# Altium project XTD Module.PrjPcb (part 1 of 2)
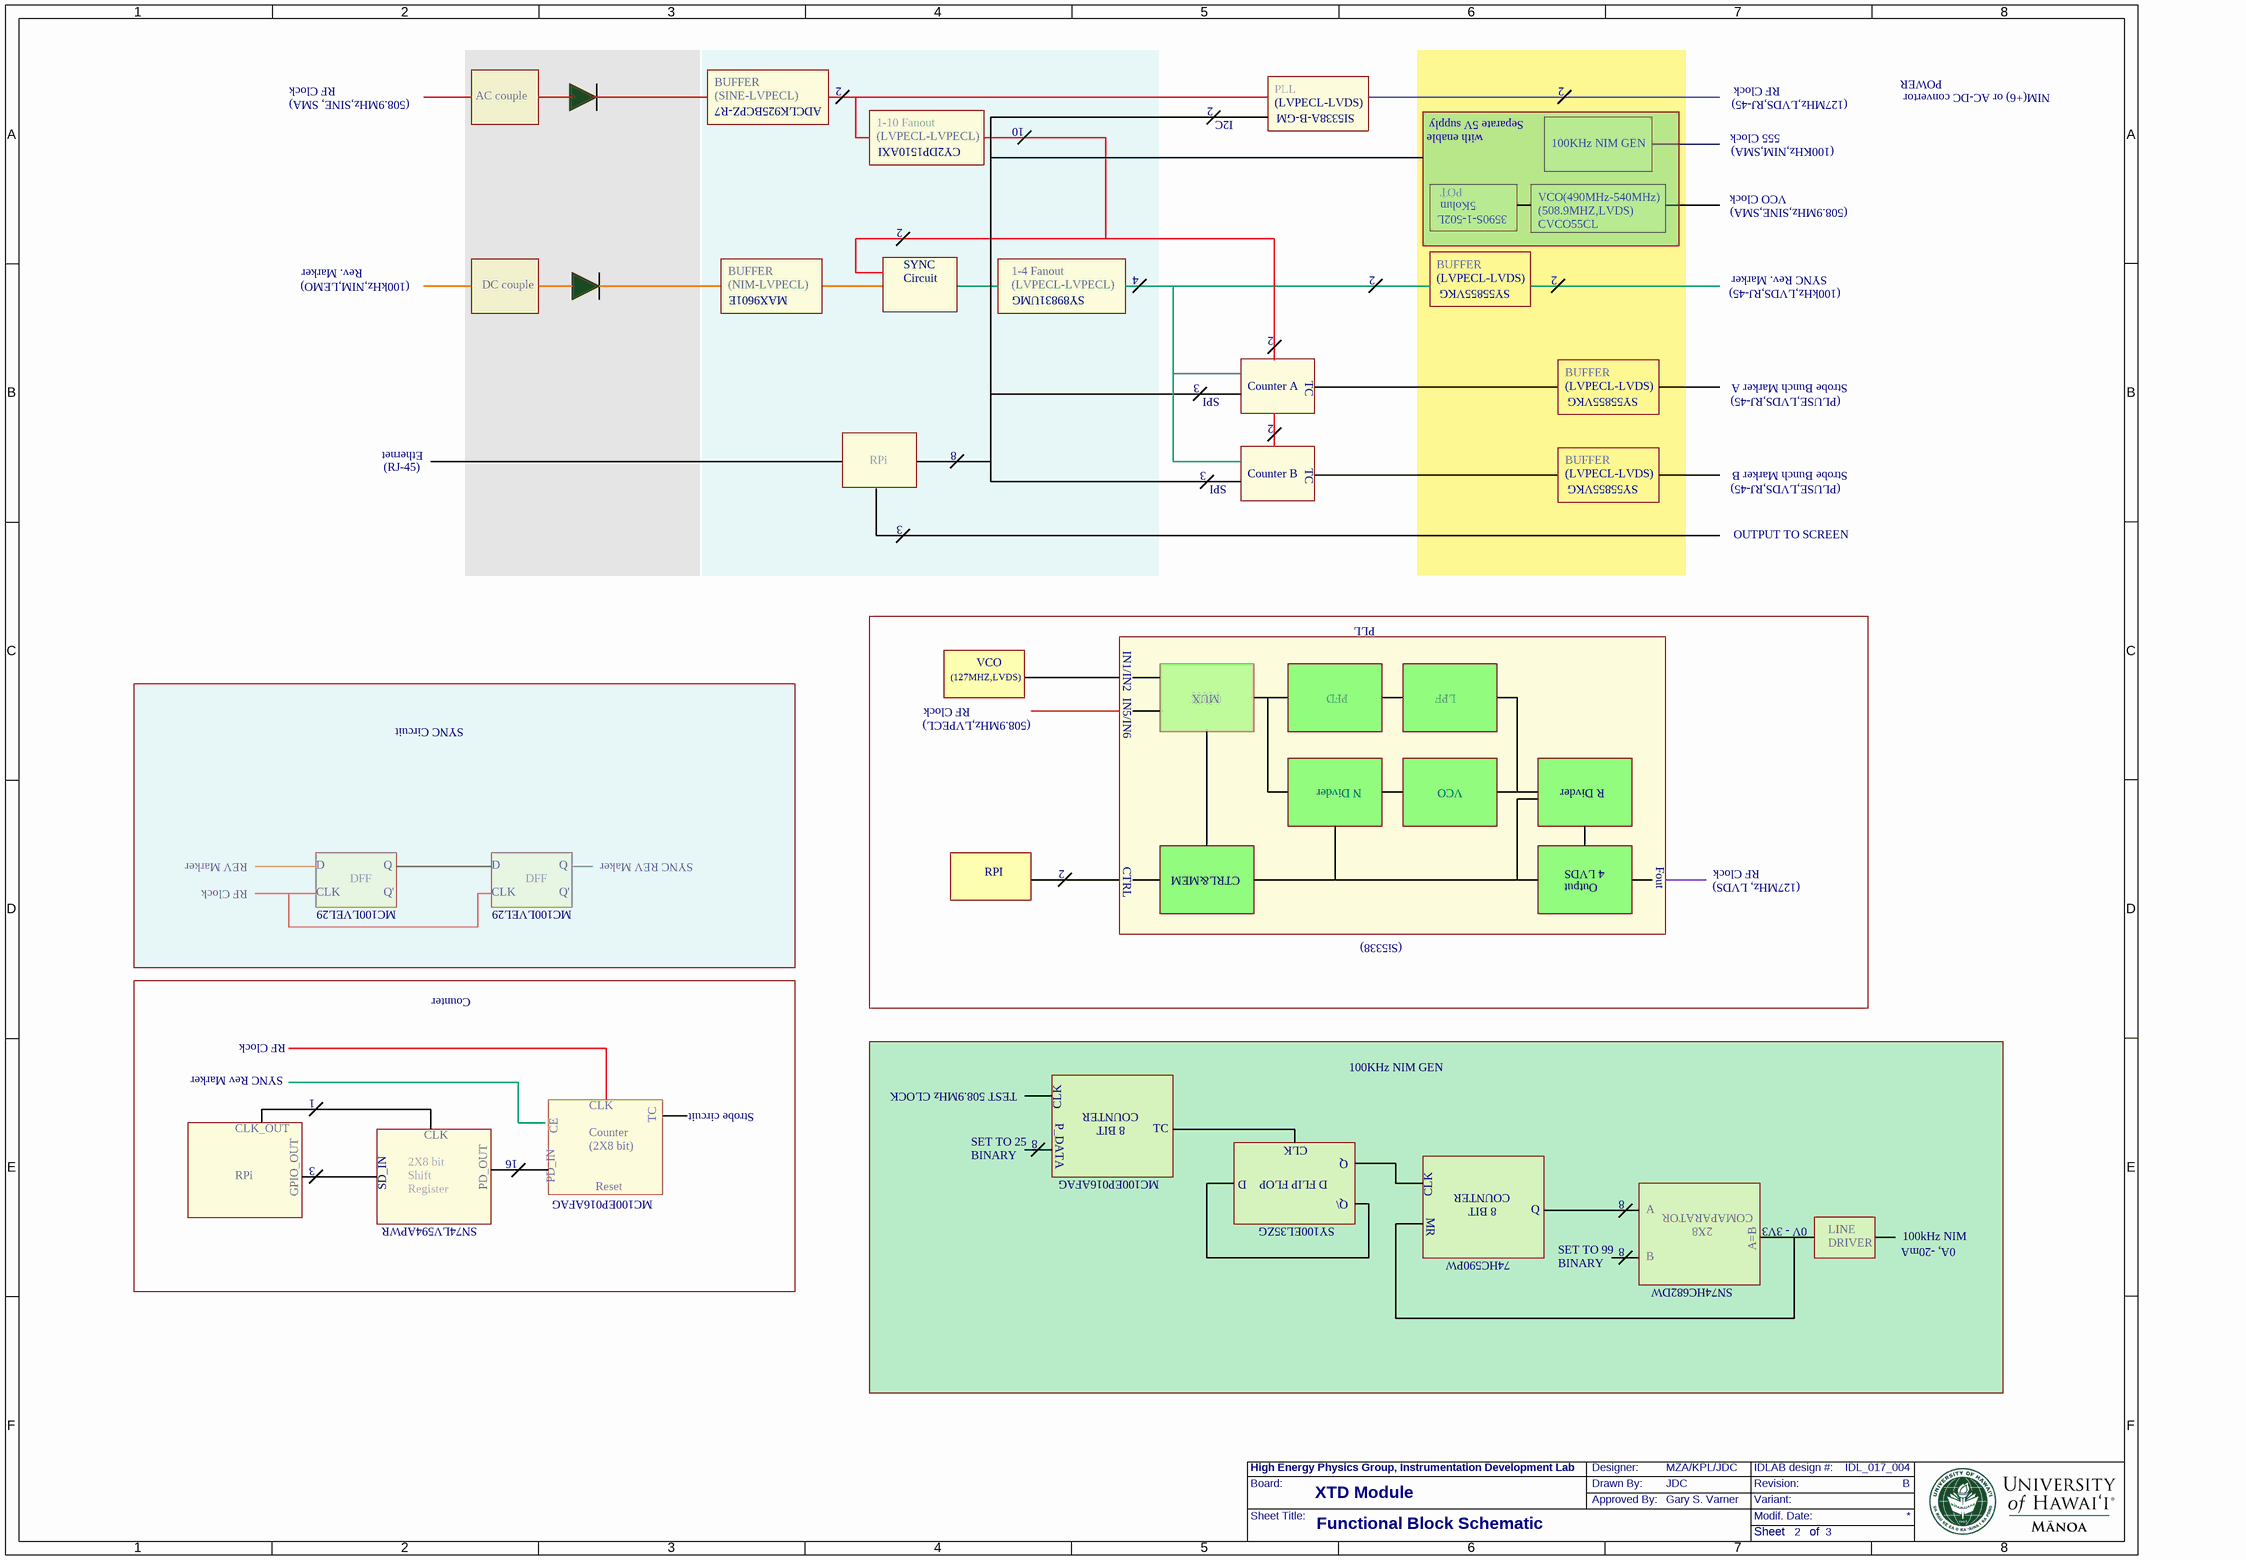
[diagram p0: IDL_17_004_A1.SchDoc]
Approved_By: Gary S. Varner; BoardName: XTD Module; Designer: MZA/KPL/JDC; Drawn_By: JDC; IDLnum: IDL_017_004; ProjectName1: XTD Module; RevNum: B
10 sheets, 403 parts. Net scope: flat (ports and power ports of the same name join across sheets).
Board file: IDL_17_004_A9.PcbDoc
Sheets:
  PRJHdr_IDL_16_XXX_A.SchDoc
  IDL_17_004_A1.SchDoc
  IDL_17_004_A2.SchDoc
  IDL_17_004_A3.SchDoc
  IDL_17_004_A4.SchDoc
  IDL_17_004_A5.SchDoc
  IDL_17_004_A6.SchDoc
  IDL_17_004_A7.SchDoc
  IDL_17_004_A8.SchDoc
  IDL_17_004_WD.SchDoc

## Sheet PRJHdr_IDL_16_XXX_A.SchDoc: Title_doc_parameter!
size 401 x 291 mm; DrawnBy: JDC; DocumentNumber: 1; Revision: B; SheetNumber: 1; SheetTotal: 3; Project_IT-Code: XXXX

## Sheet IDL_17_004_A1.SchDoc: Functional Block Schematic
size 401 x 291 mm; DocumentNumber: 2; SheetNumber: 2; SheetTotal: 3

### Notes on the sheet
- RF Clock
- (508.9MHz,SINE, SMA)
- AC couple
- BUFFER
- (SINE-LVPECL)
- ADCLK925BCPZ-R7
- 2
- PLL
- (127MHz,LVDS,RJ-45)
- POWER
- NIM(+6) or AC-DC convertor
- 1-10 Fanout
- (LVPECL-LVPECL)
- CY2DP1510AXI
- 10
- I2C
- (LVPECL-LVDS)
- SI5338A-B-GM
- with enable
- Separate 5V supply
- 100KHz NIM GEN
- 555 Clock
- (100KHz,NIM,SMA)
- POT
- 5Kohm
- 3590S-1-502L
- VCO(490MHz-540MHz)
- (508.9MHZ,LVDS)
- CVCO55CL
- VCO Clock
- (508.9MHz,SINE,SMA)
- Rev. Marker
- (100kHz,NIM,LEMO)
- DC couple
- (NIM-LVPECL)
- MAX9601E
- SYNC
- Circuit
- 1-4 Fanout
- SY89831UMG
- 4
- SY55855VKG
- SYNC Rev. Marker
- (100kHz,LVDS,RJ-45)
- 3
- SPI
- Counter A
- TC
- (PLUSE,LVDS,RJ-45)
- Strobe Bunch Marker A
- (RJ-45)
- Ethernet
- RPi
- 8
- Counter B
- Strobe Bunch Marker B
- OUTPUT TO SCREEN
- (127MHZ,LVDS)
- VCO
- IN1/IN2
- IN5/IN6
- MUX
- PFD
- LPF
- SYNC Circuit
- (508.9MHz,LVPECL)
- N Divder
- R Divder
- REV Marker
- D
- CLK
- DFF
- Q
- Q'
- MC100LVEL29
- SYNC REV Maker
- RPI
- CTRL
- CTRL&MEM
- Output
- 4 LVDS
- Fout
- (127MHz, LVDS)
- (Si5338)
- Counter
- SYNC Rev Marker
- 1
- Strobe circuit
- TEST 508.9MHz CLOCK
- COUNTER
- CLK_OUT
- Shift
- 2X8 bit
- 16
- PD_IN
- CE
- (2X8 bit)
- SET TO 25
- BINARY
- P_DATA
- 8 BIT
- MC100EP016AFAG
- D FLIP FLOP
- GPIO_OUT
- SD_IN
- Register
- SN74LV594APWR
- PD_OUT
- Reset
- SY100EL35ZG
- Q\
- MR
- A
- 2X8
- COMAPARATOR
- 0V - 3V3
- LINE
- 100kHz NIM
- 0A, -20mA
- 74HC590PW
- SET TO 99
- B
- SN74HC682DW
- A=B
- DRIVER

## Sheet IDL_17_004_A2.SchDoc: Clock Fanout
size 401 x 291 mm; Author: dfsd; DrawnBy: PO/KPL/LVV; DocumentNumber: 3; SheetNumber: 3; SheetTotal: 3
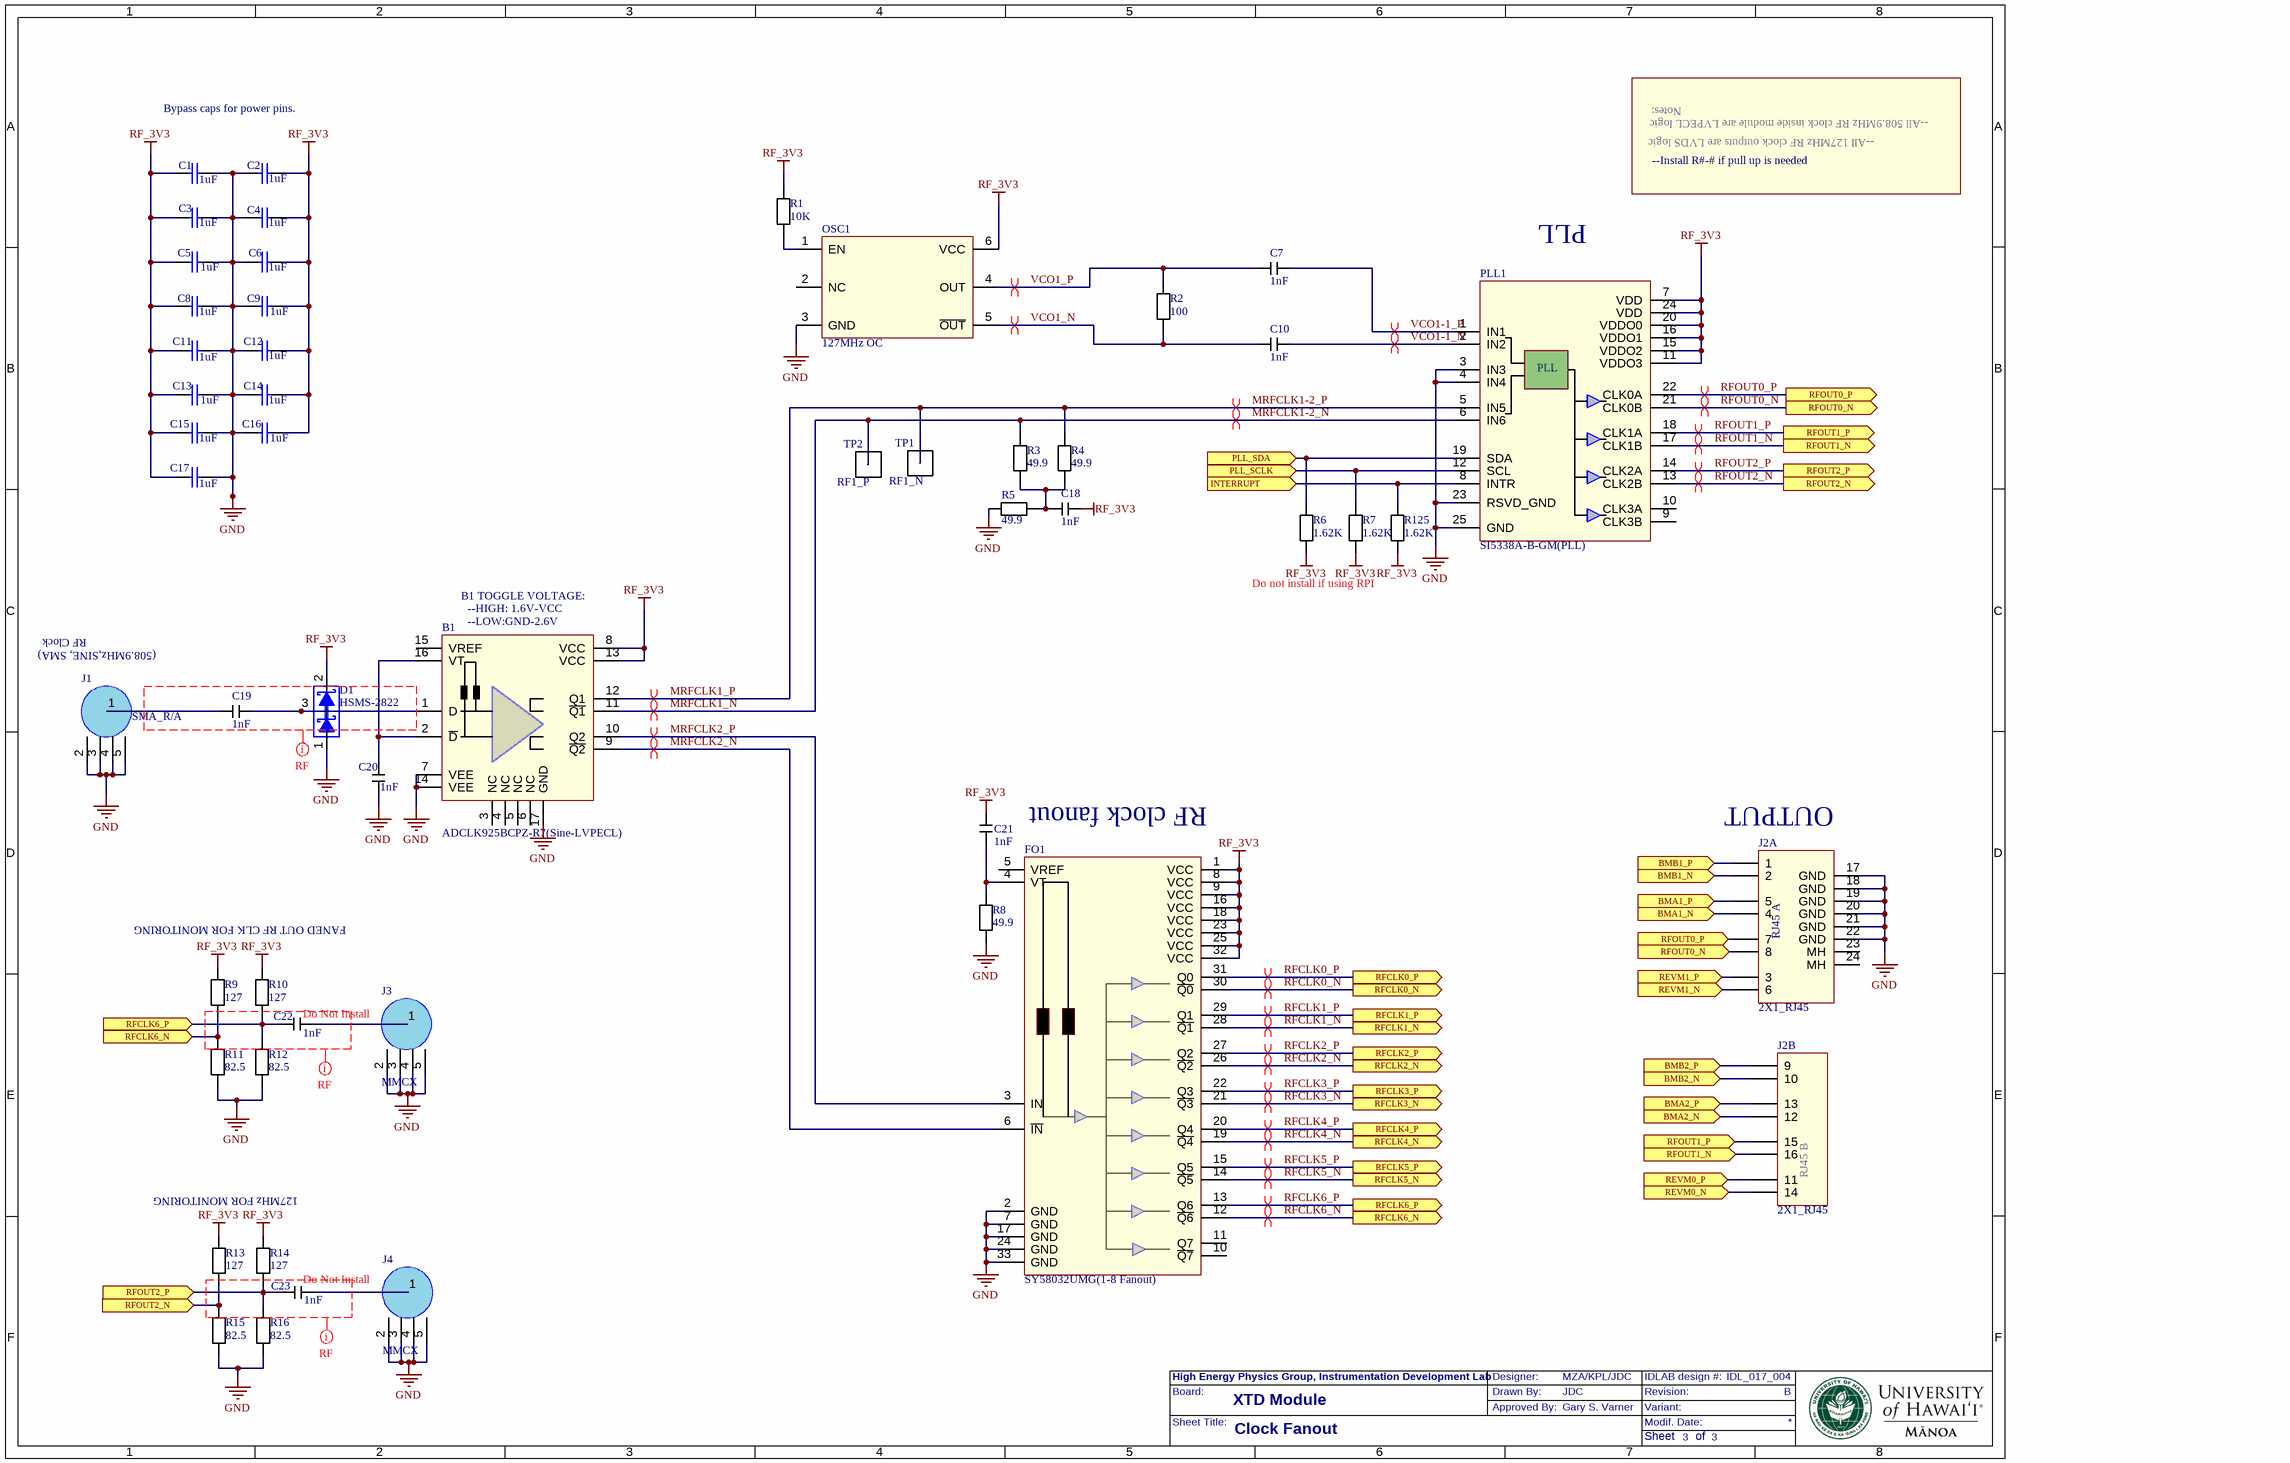
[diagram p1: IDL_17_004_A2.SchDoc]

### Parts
B1  ADCLK925BCPZ-R7(Sine-LVPECL)  [QFN_16pin]
C1  1uF  [0603]
C2  1uF  [0603]
C3  1uF  [0603]
C4  1uF  [0603]
C5  1uF  [0603]
C6  1uF  [0603]
C7  1nF  [0402]
C8  1uF  [0603]
C9  1uF  [0603]
C10  1nF  [0402]
C11  1uF  [0603]
C12  1uF  [0603]
C13  1uF  [0603]
C14  1uF  [0603]
C15  1uF  [0603]
C16  1uF  [0603]
C17  1uF  [0603]
C18  1nF  [0402]
C19  1nF  [0402]
C20  1nF  [0402]
C21  1nF  [0402]
C22  1nF  [0402]
C23  1nF  [0402]
D1  HSMS-2822  [SOT23_3pin]
FO1  SY58032UMG(1-8 Fanout)  [MLF_QFN_32PIN]
J1  SMA_R/A  [SMA_R/A]
J2  2X1_RJ45  [2X1 RJ45]  (parts A,B of 2)
J3  MMCX  [MMCX_VERTICAL_THROUGH_HOLE]
J4  MMCX  [MMCX_VERTICAL_THROUGH_HOLE]
OSC1  127MHz OC  [127MHz OC]
PLL1  SI5338A-B-GM(PLL)  [QFN_24pin]
R1  10K  [0402]
R2  100  [0402]
R3  49.9  [0402]
R4  49.9  [0402]
R5  49.9  [0402]
R6  1.62K  [0402]
R7  1.62K  [0402]
R8  49.9  [0402]
R9  127  [0402]
R10  127  [0402]
R11  82.5  [0402]
R12  82.5  [0402]
R13  127  [0402]
R14  127  [0402]
R15  82.5  [0402]
R16  82.5  [0402]
R125  1.62K  [0402]
TP1  RF1_N  [SMD_TP]
TP2  RF1_P  [SMD_TP]

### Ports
BMA1_N (in), BMA1_P (in), BMA2_N (in), BMA2_P (in), BMB1_N (in), BMB1_P (in), BMB2_N (in), BMB2_P (in), INTERRUPT (in), PLL_SCLK (in), PLL_SDA (in), REVM0_N (in), REVM0_P (in), REVM1_N (in), REVM1_P (in), RFCLK0_N (out), RFCLK0_P (out), RFCLK1_N (out), RFCLK1_P (out), RFCLK2_N (out), RFCLK2_P (out), RFCLK3_N (out), RFCLK3_P (out), RFCLK4_N (out), RFCLK4_P (out), RFCLK5_N (out), RFCLK5_P (out), RFCLK6_N (in), RFCLK6_N (out), RFCLK6_P (in), RFCLK6_P (out), RFOUT0_N (in), RFOUT0_N (out), RFOUT0_P (in), RFOUT0_P (out), RFOUT1_N (in), RFOUT1_N (out), RFOUT1_P (in), RFOUT1_P (out), RFOUT2_N (in), RFOUT2_N (out), RFOUT2_P (in), RFOUT2_P (out)

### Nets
GND: B1.7(VEE) B1.14(VEE) B1.17(GND) C1.2 C2.1 C3.2 C4.1 C5.2 C6.1 C8.2 C9.1 C11.2 C12.1 C13.2 C14.1 C15.2 C16.1 C17.2 C20.1 D1.1(A1) FO1.2(GND) FO1.7(GND) FO1.17(GND) FO1.24(GND) FO1.33(GND) J1.2 J1.3 J1.4 J1.5 J2.17(GND) J2.18(GND) J2.19(GND) J2.20(GND) J2.21(GND) J2.22(GND) J3.2 J3.3 J3.4 J3.5 J4.2 J4.3 J4.4 J4.5 OSC1.3(GND) PLL1.3(IN3) PLL1.4(IN4) PLL1.23(RSVD_GND) PLL1.25(GND) R5.2 R8.1 R11.1 R12.1 R15.1 R16.1
RF_3V3: B1.8(VCC) B1.13(VCC) C1.1 C2.2 C3.1 C4.2 C5.1 C6.2 C8.1 C9.2 C11.1 C12.2 C13.1 C14.2 C15.1 C16.2 C17.1 C18.2 C21.2 D1.2(C2) FO1.1(VCC) FO1.8(VCC) FO1.9(VCC) FO1.16(VCC) FO1.18(VCC) FO1.23(VCC) FO1.25(VCC) FO1.32(VCC) OSC1.6(VCC) PLL1.7(VDD) PLL1.11(VDDO3) PLL1.15(VDDO2) PLL1.16(VDDO1) PLL1.20(VDDO0) PLL1.24(VDD) R1.2 R6.2 R7.1 R9.2 R10.2 R13.2 R14.2 R125.1
BMA1_N: J2.4 ; port BMA1_N
BMA1_P: J2.5 ; port BMA1_P
BMA2_N: J2.12 ; port BMA2_N
BMA2_P: J2.13 ; port BMA2_P
BMB1_N: J2.2 ; port BMB1_N
BMB1_P: J2.1 ; port BMB1_P
BMB2_N: J2.10 ; port BMB2_N
BMB2_P: J2.9 ; port BMB2_P
MRFCLK1-2_N: B1.11(~{Q1}) PLL1.6(IN6) R3.2 TP2.1(TP)  [also labelled MRFCLK1_N]
MRFCLK1-2_P: B1.12(Q1) PLL1.5(IN5) R4.2 TP1.1(TP)  [also labelled MRFCLK1_P]
MRFCLK2_N: B1.9(~{Q2}) FO1.6(~{IN})
MRFCLK2_P: B1.10(Q2) FO1.3(IN)
RFCLK0_N: FO1.30(~{Q0}) ; port RFCLK0_N  [project net RFCLK0-1_N]
RFCLK0_P: FO1.31(Q0) ; port RFCLK0_P  [project net RFCLK0-1_P]
RFCLK1_N: FO1.28(~{Q1}) ; port RFCLK1_N  [project net RFCLK1-1_N]
RFCLK1_P: FO1.29(Q1) ; port RFCLK1_P  [project net RFCLK1-1_P]
RFCLK2_N: FO1.26(~{Q2}) ; port RFCLK2_N  [project net RFCLK2-1_N]
RFCLK2_P: FO1.27(Q2) ; port RFCLK2_P  [project net RFCLK2-1_P]
RFCLK3_N: FO1.21(~{Q3}) ; port RFCLK3_N  [project net RFCLK3-1_N]
RFCLK3_P: FO1.22(Q3) ; port RFCLK3_P  [project net RFCLK3-1_P]
RFCLK4_N: FO1.19(~{Q4}) ; port RFCLK4_N  [project net RFCLK4-1_N]
RFCLK4_P: FO1.20(Q4) ; port RFCLK4_P  [project net RFCLK4-1_P]
RFCLK5_N: FO1.14(~{Q5}) ; port RFCLK5_N  [project net RFCLK5-1_N]
RFCLK5_P: FO1.15(Q5) ; port RFCLK5_P  [project net RFCLK5-1_P]
RFCLK6_N: FO1.12(~{Q6}) R9.1 R11.2 ; port RFCLK6_N
RFCLK6_P: C22.1 FO1.13(Q6) R10.1 R12.2 ; port RFCLK6_P
RFOUT0_N: J2.8 PLL1.21(CLK0B) ; port RFOUT0_N
RFOUT0_P: J2.7 PLL1.22(CLK0A) ; port RFOUT0_P
RFOUT1_N: J2.16 PLL1.17(CLK1B) ; port RFOUT1_N
RFOUT1_P: J2.15 PLL1.18(CLK1A) ; port RFOUT1_P
RFOUT2_N: PLL1.13(CLK2B) R13.1 R15.2 ; port RFOUT2_N
RFOUT2_P: C23.1 PLL1.14(CLK2A) R14.1 R16.2 ; port RFOUT2_P
RMOUT0_N: J2.14 ; port REVM0_N
RMOUT0_P: J2.11 ; port REVM0_P
RMOUT1_N: J2.6 ; port REVM1_N
RMOUT1_P: J2.3 ; port REVM1_P
VCO1-1_N: C10.2 PLL1.2(IN2)
VCO1-1_P: C7.2 PLL1.1(IN1)
VCO1_N: C10.1 OSC1.5(~{OUT}) R2.1
VCO1_P: C7.1 OSC1.4(OUT) R2.2
Net*_3: PLL1.19(SDA) R6.1 ; port PLL_SDA
Net*_5: PLL1.12(SCL) R7.2 ; port PLL_SCLK
Net*_21: PLL1.8(INTR) R125.2 ; port INTERRUPT
NetB1_1: B1.1(D) C19.2 D1.3(C1A2)
NetB1_2: B1.2(~{D}) B1.16(VT) C20.2
NetC18_1: C18.1 R3.1 R4.1 R5.1
NetC19_1: C19.1 J1.1
NetC21_1: C21.1 FO1.4(VT) R8.2
NetC22_2: C22.2 J3.1
NetC23_2: C23.2 J4.1
NetOSC1_1: OSC1.1(EN) R1.1

Not connected (* = marked no-connect by the designer): B1 3(NC) 4(NC) 5(NC) 6(NC) 15(VREF); FO1 5(VREF) 10(~{Q7}) 11(Q7); J2 23(MH) 24(MH); OSC1 2(NC); PLL1 9(CLK3B) 10(CLK3A)

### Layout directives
differential pair: MRFCLK1-2_N, MRFCLK1-2_P, MRFCLK2_N, MRFCLK2_P, RFCLK0-1_N, RFCLK0-1_P, RFCLK1-1_N, RFCLK1-1_P, RFCLK2-1_N, RFCLK2-1_P, RFCLK3-1_N, RFCLK3-1_P, RFCLK4-1_N, RFCLK4-1_P, RFCLK5-1_N, RFCLK5-1_P, RFCLK6_N, RFCLK6_P, RFOUT0_N, RFOUT0_P, RFOUT1_N, RFOUT1_P, RFOUT2_N, RFOUT2_P, VCO1-1_N, VCO1-1_P, VCO1_N, VCO1_P
net class RF: (no net found under the mark)

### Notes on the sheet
- Bypass caps for power pins.
- Notes:
- --All 127MHz RF clock outputs are LVDS logic
- --All 508.9MHz RF clock inside module are LVPECL logic
- PLL
- --Install R#-# if pull up is needed
- (near B1) B1 TOGGLE VOLTAGE:
- Do not install if using RPI
- RF Clock
- (508.9MHz,SINE, SMA)
- (near B1) --HIGH: 1.6V-VCC
- (near B1) --LOW:GND-2.6V
- (near C21) RF clock fanout
- (near J2) OUTPUT
- FANED OUT RF CLK FOR MONITORING
- Do Not Install
- 127MHz FOR MONITORING

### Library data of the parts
B1 = ADCLK925BCPZ-R7(Sine-LVPECL): IC CLK BUFFER 1:2 7.5GHZ 16LFCSP; Manufacturer: Analog Devices Inc.
C1-C6 C8 C9 C11-C17 = 1uF: CAP CER 1UF 25V X7R 0603; Tech: SMDR; Voltage rating: 50V
C7 C10 C18-C23 = 1nF: CAP CER 1000PF 50V X7R 0402; Manufacturer: Samsung Electro-Mechanics America, Inc.; Manufacturer part #: CL05B102KB5NNNC
D1 = HSMS-2822(seires diode): Surface Mount RF Schottky Barrier Diodes, Series Config.; Manufacturer: Avago; Manufacturer No: HSMS-2822-TR1G; Tech: SMDR
FO1 = SY58032UMG(1-8 Fanout): IC CLK BUFFER 1:8 4GHZ 32MLF; Manufacturer: Micrel Inc.
J1 = SMA_R/A: CONN SMA JACK R/A 50 OHM PCB; Manufacturer: Molex, LLC; Manufacturer part #: 0732512201
J2 = 2X1_RJ45: CONN MOD JACK 8P8C R/A SHIELDED; Manufacturer: EDAC Inc.; Manufacturer part #: A00-216-672-450
J3 J4 = MMCX: CONN MMCX JACK STR 50 OHM PCB; Manufacturer: Molex, LLC; Manufacturer part #: 0734151471
OSC1 = 127MHz OC: OSC VCO 127.21MHZ
PLL1 = SI5338A-B-GM(PLL): IC CLK GEN I2C BUS PROG 24QFN; Manufacturer: Silicon Labs
R1 = 10K: RES SMD 10K OHM 5% 1/16W 0402; Manufacturer: Samsung Electro-Mechanics America, Inc.; Manufacturer part #: RC1005F4021CS
R2 = 100: RES SMD 100 OHM 5% 1/16W 0402; Manufacturer: Samsung Electro-Mechanics America, Inc.; Manufacturer part #: RC1005J101CS
R3-R5 R8 = 49.9: RES SMD 49.9 OHM 1% 1/16W 0402; Manufacturer: Samsung Electro-Mechanics America, Inc.; Manufacturer part #: RC1005F49R9CS
R6 R7 R125 = 1.62K: RES SMD 1.62K OHM 1% 1/16W 0402; Manufacturer: Samsung Electro-Mechanics America, Inc.; Manufacturer part #: RC1005F1621CS
R9 R10 R13 R14 = 127: RES SMD 127 OHM 1% 1/16W 0402; Manufacturer: Samsung Electro-Mechanics America, Inc.; Manufacturer part #: RC1005F1270CS
R11 R12 R15 R16 = 82.5: RES SMD 82.5 OHM 1% 1/16W 0402; Manufacturer: Samsung Electro-Mechanics America, Inc.; Manufacturer part #: RC1005F82R5CS
TP1 TP2 = SMD_TP: SURFACE MOUNT TEST POINT

## Sheet IDL_17_004_A3.SchDoc: Revalution Marker Fanout
size 401 x 291 mm
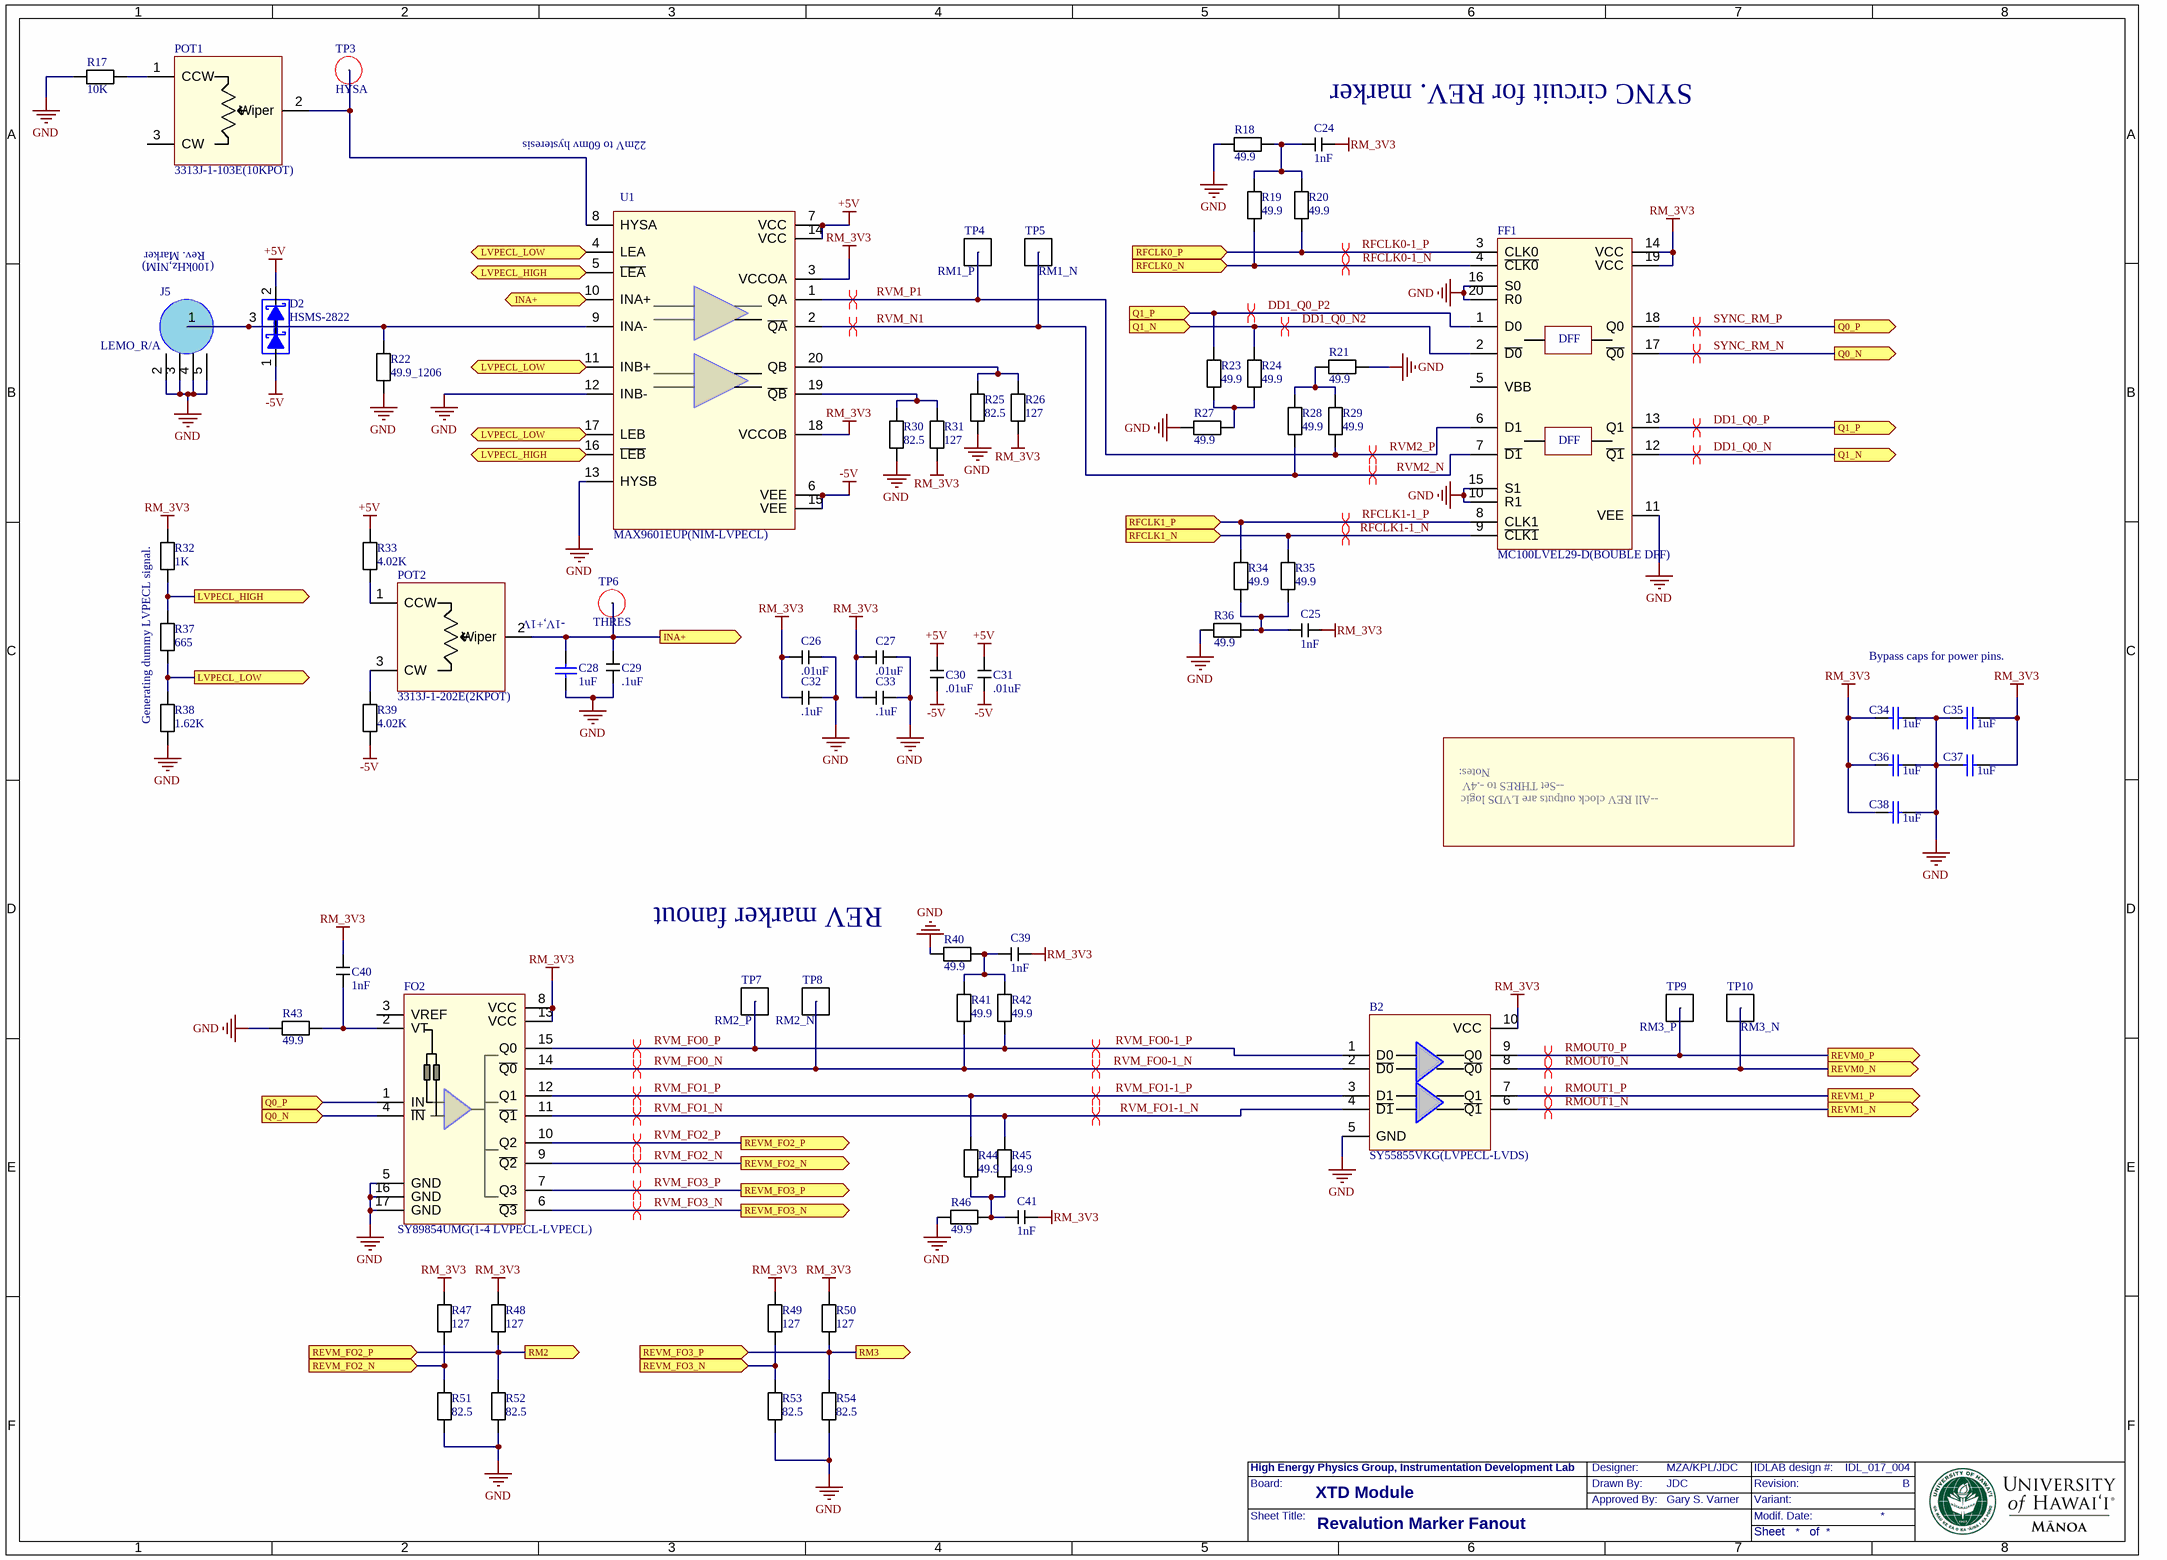
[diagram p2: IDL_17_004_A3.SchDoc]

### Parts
B2  SY55855VKG(LVPECL-LVDS)  [TFSOP_10pin]
C24  1nF  [0402]
C25  1nF  [0402]
C26  .01uF  [0603]
C27  .01uF  [0603]
C28  1uF  [0603]
C29  .1uF  [0603]
C30  .01uF  [0603]
C31  .01uF  [0603]
C32  .1uF  [0603]
C33  .1uF  [0603]
C34  1uF  [0603]
C35  1uF  [0603]
C36  1uF  [0603]
C37  1uF  [0603]
C38  1uF  [0603]
C39  1nF  [0402]
C40  1nF  [0402]
C41  1nF  [0402]
D2  HSMS-2822  [SOT23_3pin]
FF1  MC100LVEL29-D(BOUBLE DFF)  [SOIC_20pin]
FO2  SY89854UMG(1-4 LVPECL-LVPECL)  [VFQFN_16PIN]
J5  LEMO_R/A  [LEMO_R/A]
POT1  3313J-1-103E(10KPOT)  [2KPOT]
POT2  3313J-1-202E(2KPOT)  [2KPOT]
R17  10K  [0402]
R18  49.9  [0402]
R19  49.9  [0402]
R20  49.9  [0402]
R21  49.9  [0402]
R22  49.9_1206  [RC1206N1X]
R23  49.9  [0402]
R24  49.9  [0402]
R25  82.5  [0402]
R26  127  [0402]
R27  49.9  [0402]
R28  49.9  [0402]
R29  49.9  [0402]
R30  82.5  [0402]
R31  127  [0402]
R32  1K  [0402]
R33  4.02K  [0402]
R34  49.9  [0402]
R35  49.9  [0402]
R36  49.9  [0402]
R37  665  [0402]
R38  1.62K  [0402]
R39  4.02K  [0402]
R40  49.9  [0402]
R41  49.9  [0402]
R42  49.9  [0402]
R43  49.9  [0402]
R44  49.9  [0402]
R45  49.9  [0402]
R46  49.9  [0402]
R47  127  [0402]
R48  127  [0402]
R49  127  [0402]
R50  127  [0402]
R51  82.5  [0402]
R52  82.5  [0402]
R53  82.5  [0402]
R54  82.5  [0402]
TP3  HYSA  [Test Point]
TP4  RM1_P  [SMD_TP]
TP5  RM1_N  [SMD_TP]
TP6  THRES  [Test Point]
TP7  RM2_P  [SMD_TP]
TP8  RM2_N  [SMD_TP]
TP9  RM3_P  [SMD_TP]
TP10  RM3_N  [SMD_TP]
U1  MAX9601EUP(NIM-LVPECL)  [TSSOP_20pin]

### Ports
INA+ (in), INA+ (out), LVPECL_HIGH (in), LVPECL_HIGH (out), LVPECL_LOW (in), LVPECL_LOW (out), Q0_N (in), Q0_N (out), Q0_P (in), Q0_P (out), Q1_N (in), Q1_N (out), Q1_P (in), Q1_P (out), REVM0_N (out), REVM0_P (out), REVM1_N (out), REVM1_P (out), REVM_FO2_N (in), REVM_FO2_N (out), REVM_FO2_P (in), REVM_FO2_P (out), REVM_FO3_N (in), REVM_FO3_N (out), REVM_FO3_P (in), REVM_FO3_P (out), RFCLK0_N (in), RFCLK0_P (in), RFCLK1_N (in), RFCLK1_P (in), RM2 (out), RM3 (out)

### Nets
+5V: C30.2 C31.2 D2.2(C2) R33.2 U1.7(VCC) U1.14(VCC)
-5V: C30.1 C31.1 D2.1(A1) R39.1 U1.6(VEE) U1.15(VEE)
GND: B2.5(GND) C26.2 C27.2 C28.1 C29.1 C32.1 C33.1 C34.2 C35.1 C36.2 C37.1 C38.2 FF1.10(R1) FF1.11(VEE) FF1.15(S1) FF1.16(S0) FF1.20(R0) FO2.5(GND) FO2.16(GND) FO2.17(GND) J5.2 J5.3 J5.4 J5.5 R17.1 R18.2 R21.2 R22.1 R25.1 R27.1 R30.1 R36.2 R38.1 R40.2 R43.1 R46.2 R51.1 R52.1 R53.1 R54.1 U1.12(INB-) U1.13(HYSB)
RM_3V3: B2.10(VCC) C24.2 C25.2 C26.1 C27.1 C32.2 C33.2 C34.1 C35.2 C36.1 C37.2 C38.1 C39.2 C40.2 C41.2 FF1.14(VCC) FF1.19(VCC) FO2.8(VCC) FO2.13(VCC) R26.2 R31.2 R32.2 R47.2 R48.2 R49.2 R50.2 U1.3(VCCOA) U1.18(VCCOB)
DD1_Q0_N: FF1.2(~{D0}) FF1.12(~{Q1}) R24.1 ; port Q1_N  [also labelled DD1_Q0_N2]
DD1_Q0_P: FF1.1(D0) FF1.13(Q1) R23.1 ; port Q1_P  [also labelled DD1_Q0_P2]
RFCLK0-1_N: FF1.4(~{CLK0}) R19.1 ; port RFCLK0_N
RFCLK0-1_P: FF1.3(CLK0) R20.1 ; port RFCLK0_P
RFCLK1-1_N: FF1.9(~{CLK1}) R35.2 ; port RFCLK1_N
RFCLK1-1_P: FF1.8(CLK1) R34.2 ; port RFCLK1_P
RMOUT0_N: B2.8(~{Q0}) TP10.1(TP) ; port REVM0_N
RMOUT0_P: B2.9(Q0) TP9.1(TP) ; port REVM0_P
RMOUT1_N: B2.6(~{Q1}) ; port REVM1_N
RMOUT1_P: B2.7(Q1) ; port REVM1_P
RVM2_N: FF1.7(~{D1}) R28.2 TP5.1(TP) U1.2(~{QA})  [also labelled RVM_N1]
RVM2_P: FF1.6(D1) R29.2 TP4.1(TP) U1.1(QA)  [also labelled RVM_P1]
RVM_FO0-1_N: B2.2(~{D0}) FO2.14(~{Q0}) R41.1 TP8.1(TP)  [also labelled RVM_FO0_N]
RVM_FO0-1_P: B2.1(D0) FO2.15(Q0) R42.1 TP7.1(TP)  [also labelled RVM_FO0_P]
RVM_FO1-1_N: B2.4(~{D1}) FO2.11(~{Q1}) R45.2  [also labelled RVM_FO1_N]
RVM_FO1-1_P: B2.3(D1) FO2.12(Q1) R44.2  [also labelled RVM_FO1_P]
RVM_FO2_N: FO2.9(~{Q2}) R47.1 R51.2 ; port REVM_FO2_N
RVM_FO2_P: FO2.10(Q2) R48.1 R52.2 ; port RM2, port REVM_FO2_P
RVM_FO3_N: FO2.6(~{Q3}) R49.1 R53.2 ; port REVM_FO3_N
RVM_FO3_P: FO2.7(Q3) R50.1 R54.2 ; port RM3, port REVM_FO3_P
SYNC_RM_N: FF1.17(~{Q0}) FO2.4(~{IN}) ; port Q0_N
SYNC_RM_P: FF1.18(Q0) FO2.1(IN) ; port Q0_P
NetC24_1: C24.1 R18.1 R19.2 R20.2
NetC25_1: C25.1 R34.1 R35.1 R36.1
NetC28_2: C28.2 C29.2 POT2.2(Wiper) TP6.1(TP) U1.10(INA+) ; port INA+
NetC39_1: C39.1 R40.1 R41.2 R42.2
NetC40_1: C40.1 FO2.2(VT) R43.2
NetC41_1: C41.1 R44.1 R45.1 R46.1
NetD2_3: D2.3(C1A2) J5.1 R22.2 U1.9(INA-)
NetPOT1_1: POT1.1(CCW) R17.2
NetPOT1_2: POT1.2(Wiper) TP3.1(TP) U1.8(HYSA)
NetPOT2_1: POT2.1(CCW) R33.1
NetPOT2_3: POT2.3(CW) R39.2
NetR21_1: R21.1 R28.1 R29.1
NetR23_2: R23.2 R24.2 R27.2
NetR25_2: R25.2 R26.1 U1.20(QB)
NetR30_2: R30.2 R31.1 U1.19(~{QB})
NetR32_1: R32.1 R37.2 U1.5(~{LEA}) U1.16(~{LEB}) ; port LVPECL_HIGH
NetR37_1: R37.1 R38.2 U1.4(LEA) U1.11(INB+) U1.17(LEB) ; port LVPECL_LOW

Not connected (* = marked no-connect by the designer): FF1 5(VBB); FO2 3(VREF); POT1 3(CW)

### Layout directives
differential pair: DD1_Q0_N, DD1_Q0_P, RFCLK0-1_N, RFCLK0-1_P, RFCLK1-1_N, RFCLK1-1_P, RMOUT0_N, RMOUT0_P, RMOUT1_N, RMOUT1_P, RVM2_N, RVM2_P, RVM_FO0-1_N, RVM_FO0-1_P, RVM_FO1-1_N, RVM_FO1-1_P, RVM_FO2_N, RVM_FO2_P, RVM_FO3_N, RVM_FO3_P, SYNC_RM_N, SYNC_RM_P

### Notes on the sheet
- SYNC circuit for REV. marker
- 22mV to 60mv hysteresis
- Rev. Marker
- (100kHz,NIM)
- (near POT2) -1V,+1V
- Bypass caps for power pins.
- Generating dummy LVPECL signal.
- Notes:
- --Set THRES to -.4V
- --All REV clock outputs are LVDS logic
- REV marker fanout

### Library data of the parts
B2 = SY55855VKG(LVPECL-LVDS): IC TRANSLATOR DUAL LVDS 10MSOP; Manufacturer: Micrel Inc.
C24 C25 C39-C41 = 1nF: as C7 on sheet IDL_17_004_A2
C26 C27 C30 C31 = .01uF: CAP CER 10000PF 50V X7R 0603; Manufacturer: Samsung Electro-Mechanics America, Inc.; Manufacturer part #: CL10B103KB8NCNC
C28 C34-C38 = 1uF: as C1 on sheet IDL_17_004_A2
C29 C32 C33 = .1uF: CAP CER 0.1UF 50V X7R 0603; Manufacturer: Samsung Electro-Mechanics America, Inc.; Manufacturer part: CL10B104KB8SFNC
D2 = HSMS-2822(seires diode): as D1 on sheet IDL_17_004_A2
FF1 = MC100LVEL29-D(BOUBLE DFF): IC D-TYPE POS TRG DUAL 20SOIC; Manufacturer: ON Semiconductor; Manufacturer part #: MC100LVEL29DWG
FO2 = SY89854UMG(1-4 LVPECL-LVPECL): IC CLK BUFFER 1:4 3.5GHZ 16MLF; Manufacturer: Micrel Inc.
J5 = LEMO_R/A: CONN JACK R/A 50 OHM PCB; Manufacturer: LEMO; Manufacturer part #: EPL.00.250.NTN
POT1 = 3313J-1-103E(10KPOT): TRIMMER 10K OHM 0.125W SMD; Manufacturer: Bourns Inc.
POT2 = 3313J-1-202E(2KPOT): TRIMMER 2K OHM 0.125W SMD; Manufacturer: Bourns Inc.
R17 = 10K: as R1 on sheet IDL_17_004_A2
R18-R21 R23 R24 R27-R29 R34-R36 R40-R46 = 49.9: as R3 on sheet IDL_17_004_A2
R22 = 49.9_1206: RES SMD 49.9 OHM 1% 1/2W 1206; Manufacturer: Stackpole Electronics Inc.; Manufacturer part #: RNCP1206FTD49R9
R25 R30 R51-R54 = 82.5: as R11 on sheet IDL_17_004_A2
R26 R31 R47-R50 = 127: as R9 on sheet IDL_17_004_A2
R32 = 1K: RES SMD 1K OHM 5% 1/16W 0402; Manufacturer: Samsung Electro-Mechanics America, Inc.; Manufacturer part #: RC1005J102CS
R33 R39 = 4.02K: RES SMD 4.02K OHM 1% 1/16W 0402; Manufacturer: Samsung Electro-Mechanics America, Inc.; Manufacturer part #: RC1005F4021CS
R37 = 665: RES SMD 665 OHM 1% 1/16W 0402; Manufacturer: Samsung Electro-Mechanics America, Inc.; Manufacturer part #: RC1005F6650CS
R38 = 1.62K: as R6 on sheet IDL_17_004_A2
TP3 TP6 = Test point: TEST POINT PC MINI .040"D BLACK; Manufacturer: Keystone Electronics; Manufacturer part #: 5001
TP4 TP5 TP7-TP10 = SMD_TP: SURFACE MOUNT TEST POINT
U1 = MAX9601EUP(NIM-LVPECL): IC COMPARATOR HS 20-TSSOP; Manufacturer: Maxim Integrated; Manufacturer part #: MAX9601EUP+

## Sheet IDL_17_004_A4.SchDoc: Counter A and B
size 401 x 291 mm; DocumentNumber: 3; SheetNumber: 3; SheetTotal: 3
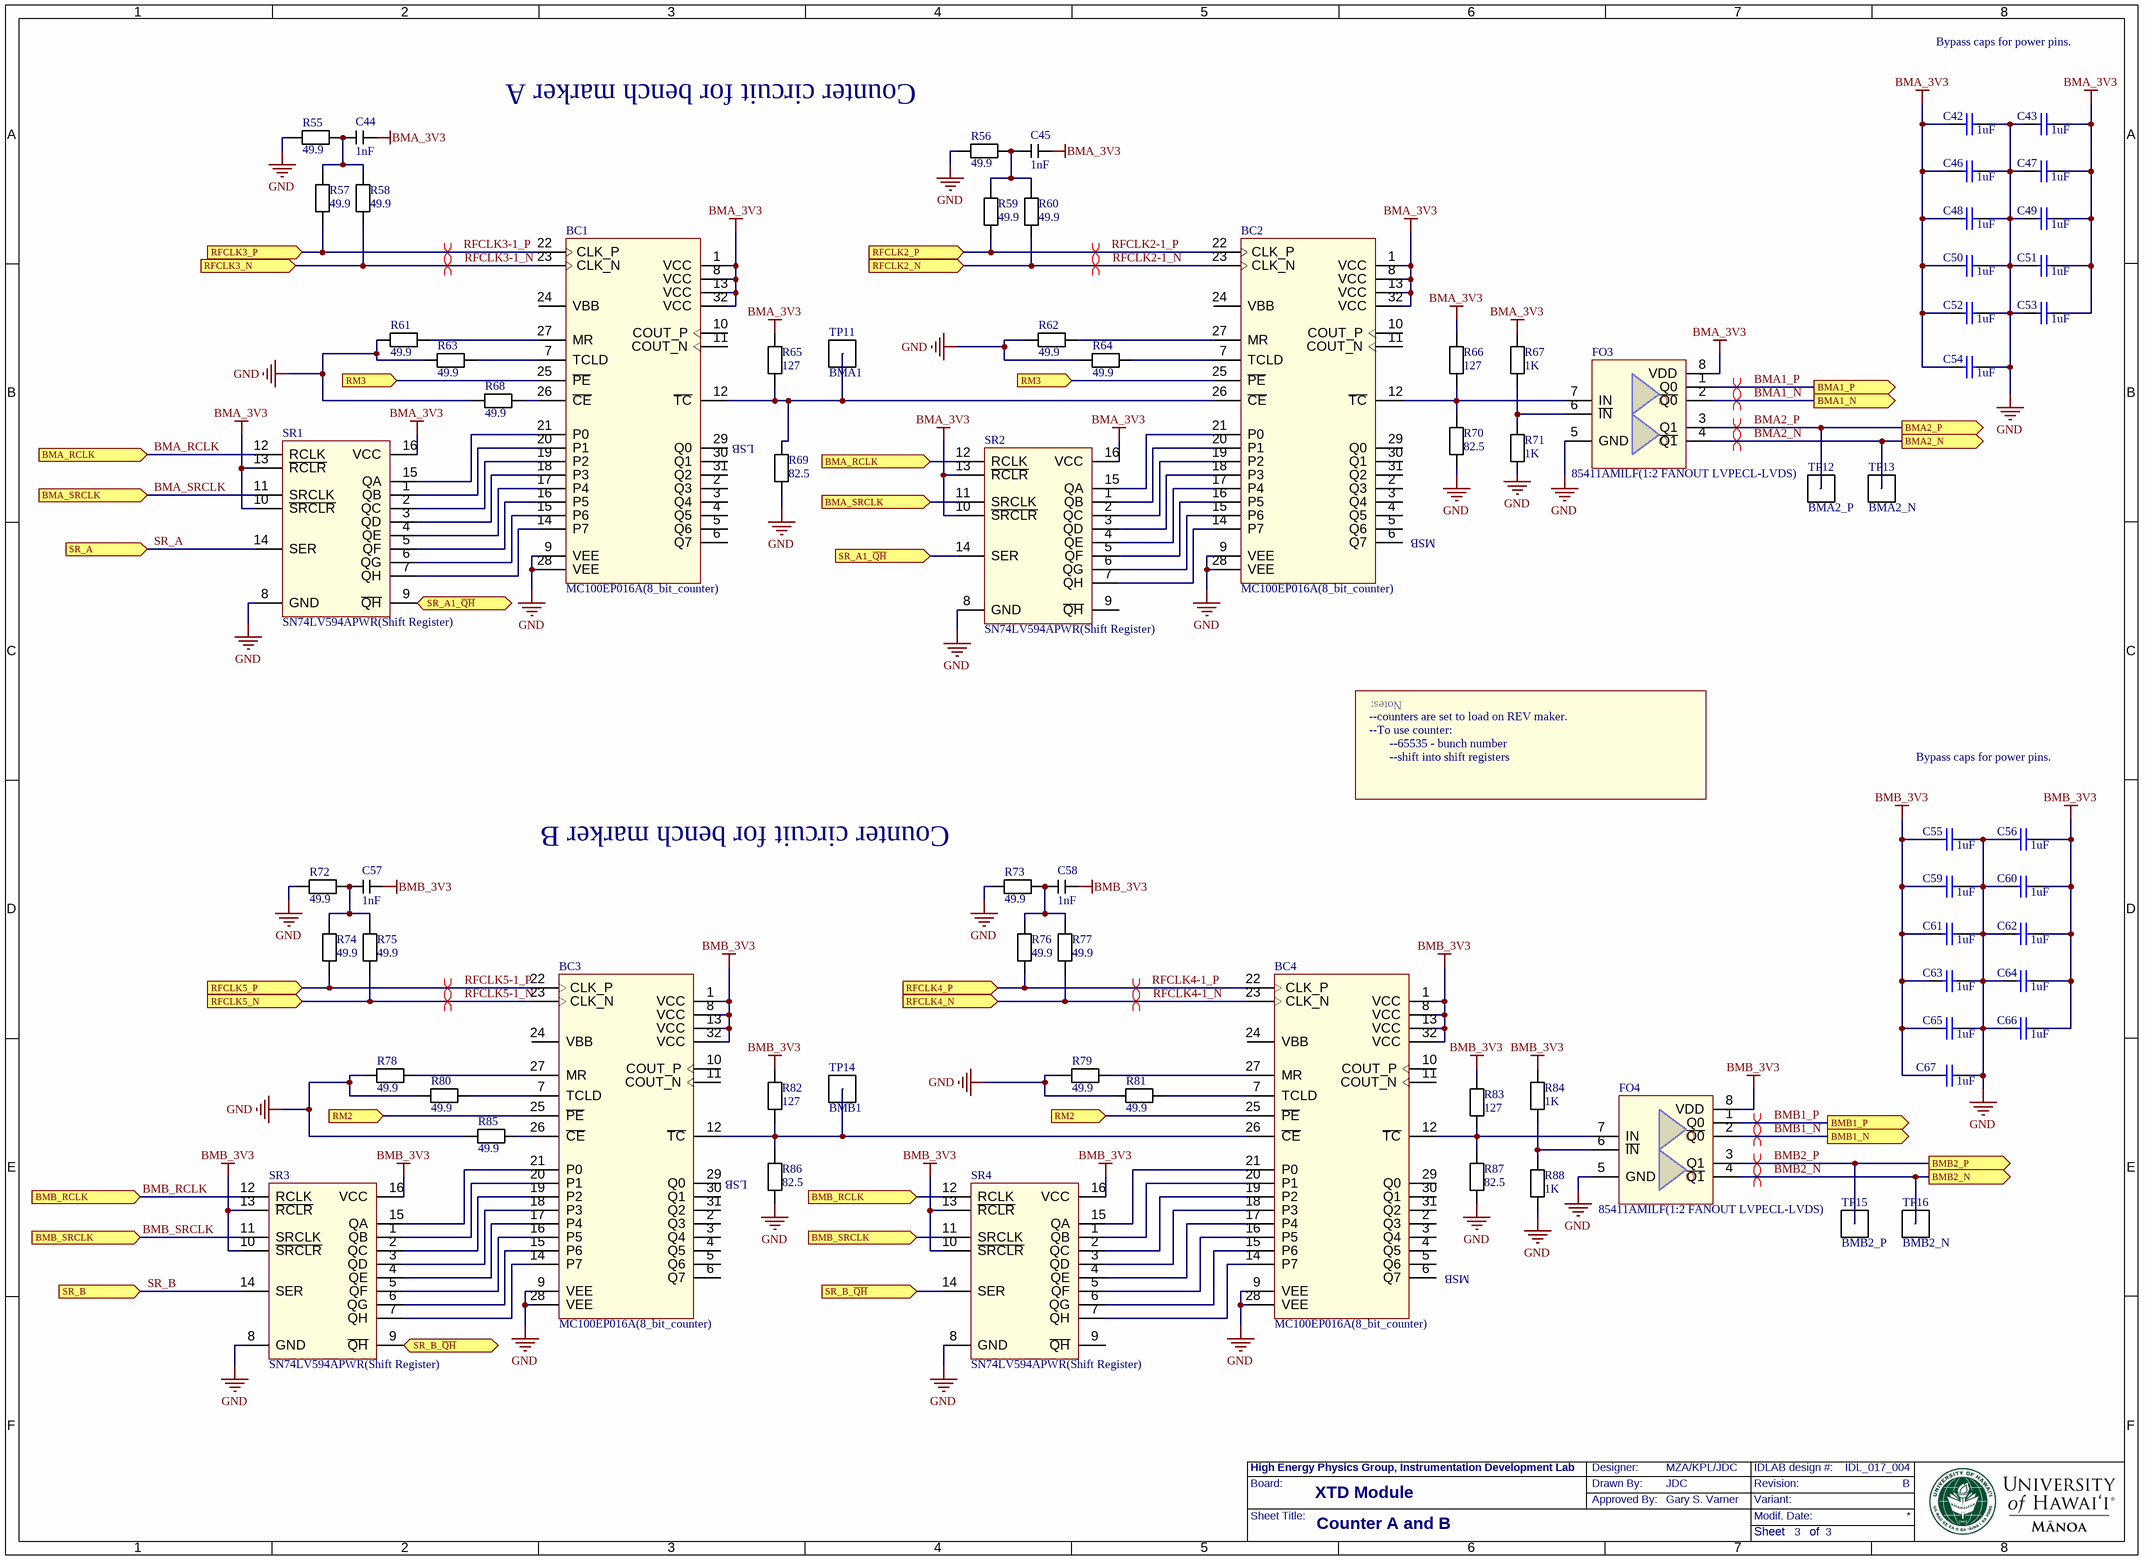
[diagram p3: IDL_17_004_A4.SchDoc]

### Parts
BC1  MC100EP016A(8_bit_counter)  [LQFP_32pin]
BC2  MC100EP016A(8_bit_counter)  [LQFP_32pin]
BC3  MC100EP016A(8_bit_counter)  [LQFP_32pin]
BC4  MC100EP016A(8_bit_counter)  [LQFP_32pin]
C42  1uF  [0603]
C43  1uF  [0603]
C44  1nF  [0402]
C45  1nF  [0402]
C46  1uF  [0603]
C47  1uF  [0603]
C48  1uF  [0603]
C49  1uF  [0603]
C50  1uF  [0603]
C51  1uF  [0603]
C52  1uF  [0603]
C53  1uF  [0603]
C54  1uF  [0603]
C55  1uF  [0603]
C56  1uF  [0603]
C57  1nF  [0402]
C58  1nF  [0402]
C59  1uF  [0603]
C60  1uF  [0603]
C61  1uF  [0603]
C62  1uF  [0603]
C63  1uF  [0603]
C64  1uF  [0603]
C65  1uF  [0603]
C66  1uF  [0603]
C67  1uF  [0603]
FO3  85411AMILF(1:2 FANOUT LVPECL-LVDS)  [SOIC_8pin]
FO4  85411AMILF(1:2 FANOUT LVPECL-LVDS)  [SOIC_8pin]
R55  49.9  [0402]
R56  49.9  [0402]
R57  49.9  [0402]
R58  49.9  [0402]
R59  49.9  [0402]
R60  49.9  [0402]
R61  49.9  [0402]
R62  49.9  [0402]
R63  49.9  [0402]
R64  49.9  [0402]
R65  127  [0402]
R66  127  [0402]
R67  1K  [0402]
R68  49.9  [0402]
R69  82.5  [0402]
R70  82.5  [0402]
R71  1K  [0402]
R72  49.9  [0402]
R73  49.9  [0402]
R74  49.9  [0402]
R75  49.9  [0402]
R76  49.9  [0402]
R77  49.9  [0402]
R78  49.9  [0402]
R79  49.9  [0402]
R80  49.9  [0402]
R81  49.9  [0402]
R82  127  [0402]
R83  127  [0402]
R84  1K  [0402]
R85  49.9  [0402]
R86  82.5  [0402]
R87  82.5  [0402]
R88  1K  [0402]
SR1  SN74LV594APWR(Shift Register)  [TSSOP_16pin]
SR2  SN74LV594APWR(Shift Register)  [TSSOP_16pin]
SR3  SN74LV594APWR(Shift Register)  [TSSOP_16pin]
SR4  SN74LV594APWR(Shift Register)  [TSSOP_16pin]
TP11  BMA1  [SMD_TP]
TP12  BMA2_P  [SMD_TP]
TP13  BMA2_N  [SMD_TP]
TP14  BMB1  [SMD_TP]
TP15  BMB2_P  [SMD_TP]
TP16  BMB2_N  [SMD_TP]

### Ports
BMA1_N (out), BMA1_P (out), BMA2_N (out), BMA2_P (out), BMA_RCLK (in), BMA_SRCLK (in), BMB1_N (out), BMB1_P (out), BMB2_N (out), BMB2_P (out), BMB_RCLK (in), BMB_SRCLK (in), RFCLK2_N (in), RFCLK2_P (in), RFCLK3_N (in), RFCLK3_P (in), RFCLK4_N (in), RFCLK4_P (in), RFCLK5_N (in), RFCLK5_P (in), RM2 (in), RM3 (in), SR_A1_~{QH} (in), SR_A1_~{QH} (out), SR_A (in), SR_B (in), SR_B_~{QH} (in), SR_B_~{QH} (out)

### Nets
BMA_3V3: BC1.1(VCC) BC1.8(VCC) BC1.13(VCC) BC1.32(VCC) BC2.1(VCC) BC2.8(VCC) BC2.13(VCC) BC2.32(VCC) C42.1 C43.2 C44.2 C45.2 C46.1 C47.2 C48.1 C49.2 C50.1 C51.2 C52.1 C53.2 C54.1 FO3.8(VDD) R65.2 R66.2 R67.2 SR1.10(~{SRCLR}) SR1.13(~{RCLR}) SR1.16(VCC) SR2.10(~{SRCLR}) SR2.13(~{RCLR}) SR2.16(VCC)
BMB_3V3: BC3.1(VCC) BC3.8(VCC) BC3.13(VCC) BC3.32(VCC) BC4.1(VCC) BC4.8(VCC) BC4.13(VCC) BC4.32(VCC) C55.1 C56.2 C57.2 C58.2 C59.1 C60.2 C61.1 C62.2 C63.1 C64.2 C65.1 C66.2 C67.1 FO4.8(VDD) R82.2 R83.1 R84.2 SR3.10(~{SRCLR}) SR3.13(~{RCLR}) SR3.16(VCC) SR4.10(~{SRCLR}) SR4.13(~{RCLR}) SR4.16(VCC)
GND: BC1.9(VEE) BC1.28(VEE) BC2.9(VEE) BC2.28(VEE) BC3.9(VEE) BC3.28(VEE) BC4.9(VEE) BC4.28(VEE) C42.2 C43.1 C46.2 C47.1 C48.2 C49.1 C50.2 C51.1 C52.2 C53.1 C54.2 C55.2 C56.1 C59.2 C60.1 C61.2 C62.1 C63.2 C64.1 C65.2 C66.1 C67.2 FO3.5(GND) FO4.5(GND) R55.1 R56.1 R61.2 R62.2 R63.2 R64.2 R68.2 R69.2 R70.2 R71.2 R72.1 R73.1 R78.2 R79.2 R80.2 R81.2 R85.2 R86.2 R87.2 R88.2 SR1.8(GND) SR2.8(GND) SR3.8(GND) SR4.8(GND)
BMA1_N: FO3.2(~{Q0}) ; port BMA1_N
BMA1_P: FO3.1(Q0) ; port BMA1_P
BMA2_N: FO3.4(~{Q1}) TP13.1(TP) ; port BMA2_N
BMA2_P: FO3.3(Q1) TP12.1(TP) ; port BMA2_P
BMA_RCLK: SR1.12(RCLK) SR2.12(RCLK) ; port BMA_RCLK
BMA_SRCLK: SR1.11(SRCLK) SR2.11(SRCLK) ; port BMA_SRCLK
BMB1_N: FO4.2(~{Q0}) ; port BMB1_N
BMB1_P: FO4.1(Q0) ; port BMB1_P
BMB2_N: FO4.4(~{Q1}) TP16.1(TP) ; port BMB2_N
BMB2_P: FO4.3(Q1) TP15.1(TP) ; port BMB2_P
BMB_RCLK: SR3.12(RCLK) SR4.12(RCLK) ; port BMB_RCLK
BMB_SRCLK: SR3.11(SRCLK) SR4.11(SRCLK) ; port BMB_SRCLK
RFCLK2-1_N: BC2.23(CLK_N) R60.1 ; port RFCLK2_N
RFCLK2-1_P: BC2.22(CLK_P) R59.1 ; port RFCLK2_P
RFCLK3-1_N: BC1.23(CLK_N) R58.1 ; port RFCLK3_N
RFCLK3-1_P: BC1.22(CLK_P) R57.1 ; port RFCLK3_P
RFCLK4-1_N: BC4.23(CLK_N) R77.1 ; port RFCLK4_N
RFCLK4-1_P: BC4.22(CLK_P) R76.1 ; port RFCLK4_P
RFCLK5-1_N: BC3.23(CLK_N) R75.1 ; port RFCLK5_N
RFCLK5-1_P: BC3.22(CLK_P) R74.1 ; port RFCLK5_P
RVM_FO2_P: BC3.25(~{PE}) BC4.25(~{PE}) ; port RM2
RVM_FO3_P: BC1.25(~{PE}) BC2.25(~{PE}) ; port RM3
SR_A: SR1.14(SER) ; port SR_A
SR_B: SR3.14(SER) ; port SR_B
NetBC1_7: BC1.7(TCLD) R63.1
NetBC1_12: BC1.12(~{TC}) BC2.26(~{CE}) R65.1 R69.1 TP11.1(TP)
NetBC1_14: BC1.14(P7) SR1.7(QH)
NetBC1_15: BC1.15(P6) SR1.6(QG)
NetBC1_16: BC1.16(P5) SR1.5(QF)
NetBC1_17: BC1.17(P4) SR1.4(QE)
NetBC1_18: BC1.18(P3) SR1.3(QD)
NetBC1_19: BC1.19(P2) SR1.2(QC)
NetBC1_20: BC1.20(P1) SR1.1(QB)
NetBC1_21: BC1.21(P0) SR1.15(QA)
NetBC1_26: BC1.26(~{CE}) R68.1
NetBC1_27: BC1.27(MR) R61.1
NetBC2_7: BC2.7(TCLD) R64.1
NetBC2_12: BC2.12(~{TC}) FO3.7(IN) R66.1 R70.1
NetBC2_14: BC2.14(P7) SR2.7(QH)
NetBC2_15: BC2.15(P6) SR2.6(QG)
NetBC2_16: BC2.16(P5) SR2.5(QF)
NetBC2_17: BC2.17(P4) SR2.4(QE)
NetBC2_18: BC2.18(P3) SR2.3(QD)
NetBC2_19: BC2.19(P2) SR2.2(QC)
NetBC2_20: BC2.20(P1) SR2.1(QB)
NetBC2_21: BC2.21(P0) SR2.15(QA)
NetBC2_27: BC2.27(MR) R62.1
NetBC3_7: BC3.7(TCLD) R80.1
NetBC3_12: BC3.12(~{TC}) BC4.26(~{CE}) R82.1 R86.1 TP14.1(TP)
NetBC3_14: BC3.14(P7) SR3.7(QH)
NetBC3_15: BC3.15(P6) SR3.6(QG)
NetBC3_16: BC3.16(P5) SR3.5(QF)
NetBC3_17: BC3.17(P4) SR3.4(QE)
NetBC3_18: BC3.18(P3) SR3.3(QD)
NetBC3_19: BC3.19(P2) SR3.2(QC)
NetBC3_20: BC3.20(P1) SR3.1(QB)
NetBC3_21: BC3.21(P0) SR3.15(QA)
NetBC3_26: BC3.26(~{CE}) R85.1
NetBC3_27: BC3.27(MR) R78.1
NetBC4_7: BC4.7(TCLD) R81.1
NetBC4_12: BC4.12(~{TC}) FO4.7(IN) R83.2 R87.1
NetBC4_14: BC4.14(P7) SR4.7(QH)
NetBC4_15: BC4.15(P6) SR4.6(QG)
NetBC4_16: BC4.16(P5) SR4.5(QF)
NetBC4_17: BC4.17(P4) SR4.4(QE)
NetBC4_18: BC4.18(P3) SR4.3(QD)
NetBC4_19: BC4.19(P2) SR4.2(QC)
NetBC4_20: BC4.20(P1) SR4.1(QB)
NetBC4_21: BC4.21(P0) SR4.15(QA)
NetBC4_27: BC4.27(MR) R79.1
NetC44_1: C44.1 R55.2 R57.2 R58.2
NetC45_1: C45.1 R56.2 R59.2 R60.2
NetC57_1: C57.1 R72.2 R74.2 R75.2
NetC58_1: C58.1 R73.2 R76.2 R77.2
NetFO3_6: FO3.6(~{IN}) R67.1 R71.1
NetFO4_6: FO4.6(~{IN}) R84.1 R88.1
NetSR1_9: SR1.9(~{QH}) SR2.14(SER) ; port SR_A1_~{QH}
NetSR3_9: SR3.9(~{QH}) SR4.14(SER) ; port SR_B_~{QH}

Not connected (* = marked no-connect by the designer): BC1 2(Q3) 3(Q4) 4(Q5) 5(Q6) 6(Q7) 10(COUT_P) 11(COUT_N) 24(VBB) 29(Q0) 30(Q1) 31(Q2); BC2 2(Q3) 3(Q4) 4(Q5) 5(Q6) 6(Q7) 10(COUT_P) 11(COUT_N) 24(VBB) 29(Q0) 30(Q1) 31(Q2); BC3 2(Q3) 3(Q4) 4(Q5) 5(Q6) 6(Q7) 10(COUT_P) 11(COUT_N) 24(VBB) 29(Q0) 30(Q1) 31(Q2); BC4 2(Q3) 3(Q4) 4(Q5) 5(Q6) 6(Q7) 10(COUT_P) 11(COUT_N) 24(VBB) 29(Q0) 30(Q1) 31(Q2); SR2 9(~{QH}); SR4 9(~{QH})

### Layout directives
differential pair: BMA1_N, BMA1_P, BMA2_N, BMA2_P, BMB1_N, BMB1_P, BMB2_N, BMB2_P, RFCLK2-1_N, RFCLK2-1_P, RFCLK3-1_N, RFCLK3-1_P, RFCLK4-1_N, RFCLK4-1_P, RFCLK5-1_N, RFCLK5-1_P

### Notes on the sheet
- Counter circuit for bench marker A
- Bypass caps for power pins.
- LSB
- (near BC2) MSB
- Notes:
- --To use counter:
- --counters are set to load on REV maker.
- --65535 - bunch number
- --shift into shift registers
- Counter circuit for bench marker B
- (near BC4) MSB

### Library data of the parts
BC1-BC4 = MC100EP016A(8_bit_counter): IC COUNTER 8BIT SYNC ECL 32LQFP; Manufacturer: ON Semiconductor; Manufacturer part #: MC100EP016AFAG
C42 C43 C46-C56 C59-C67 = 1uF: as C1 on sheet IDL_17_004_A2
C44 C45 C57 C58 = 1nF: as C7 on sheet IDL_17_004_A2
FO3 FO4 = 85411AMILF(1:2 FANOUT LVPECL-LVDS): IC CLK BUFFER 1:2 650MHZ 8SOIC; Manufacturer: IDT, Integrated Device Technology Inc
R55-R64 R68 R72-R81 R85 = 49.9: as R3 on sheet IDL_17_004_A2
R65 R66 R82 R83 = 127: as R9 on sheet IDL_17_004_A2
R67 R71 R84 R88 = 1K: as R32 on sheet IDL_17_004_A3
R69 R70 R86 R87 = 82.5: as R11 on sheet IDL_17_004_A2
SR1-SR4 = SN74LV594APWR(Shift Register): IC 8-BIT SHFT REG W/OUT 16-TSSOP; Manufacturer: Texas Instruments
TP11-TP16 = SMD_TP: SURFACE MOUNT TEST POINT

## Sheet IDL_17_004_A5.SchDoc: Test Clock Gen
size 401 x 291 mm; DocumentNumber: 3; SheetNumber: 3; SheetTotal: 3
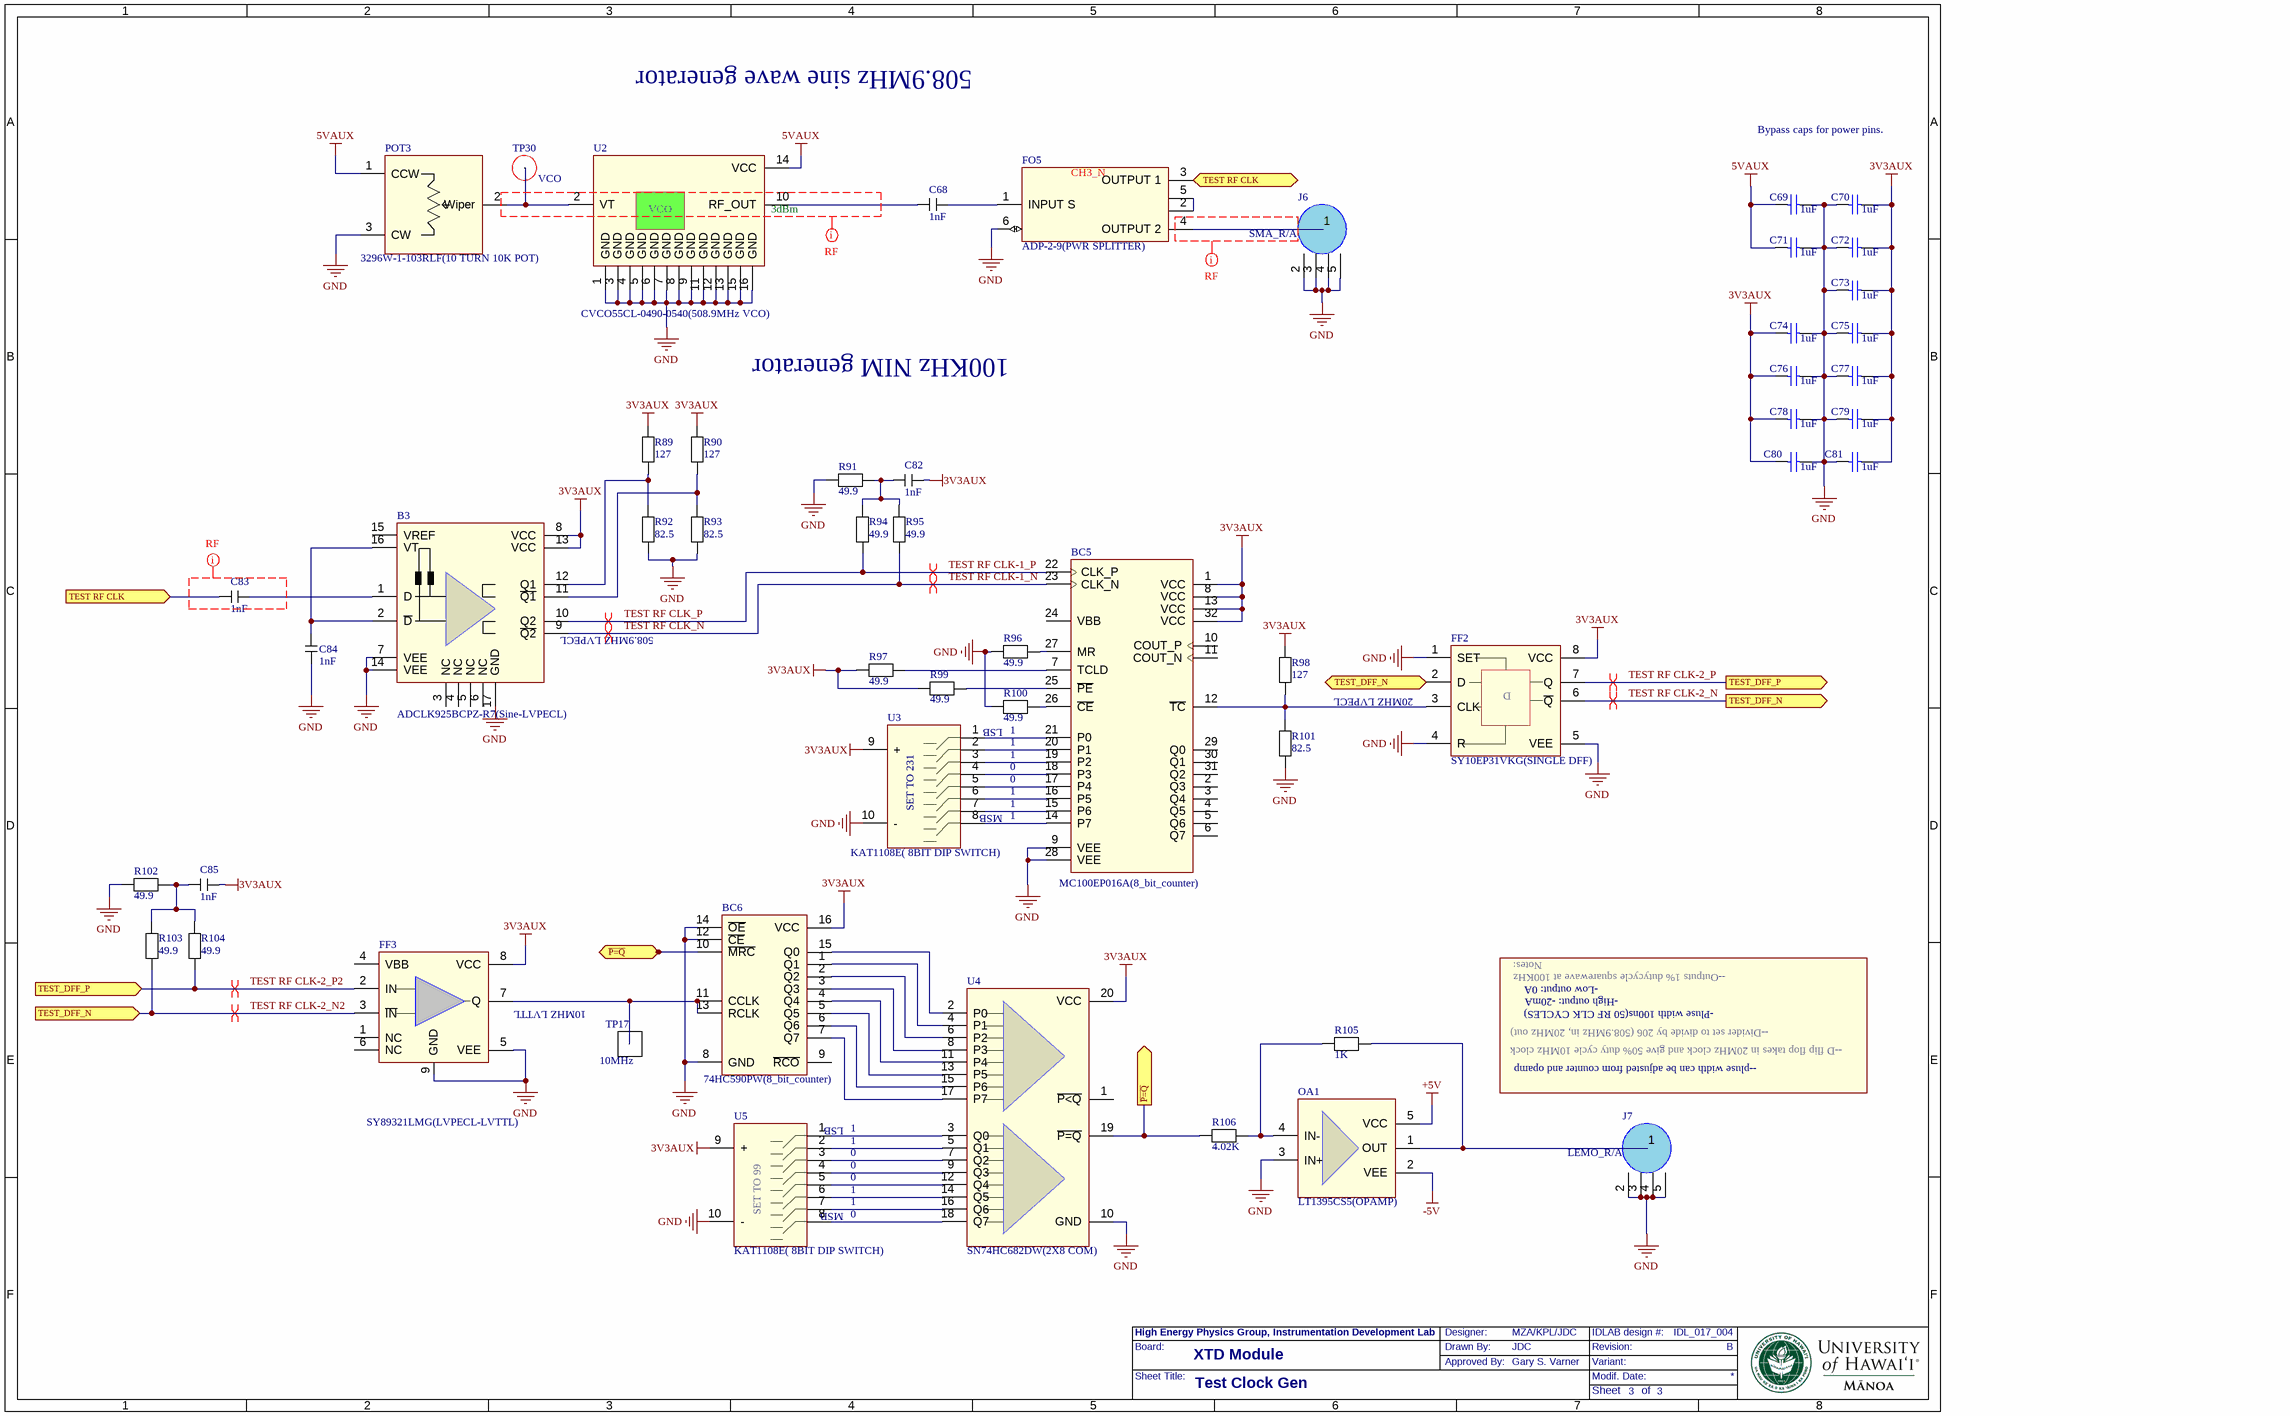
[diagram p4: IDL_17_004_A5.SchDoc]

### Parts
B3  ADCLK925BCPZ-R7(Sine-LVPECL)  [QFN_16pin]
BC5  MC100EP016A(8_bit_counter)  [LQFP_32pin]
BC6  74HC590PW(8_bit_counter)  [TSSOP_16pin]
C68  1nF  [0402]
C69  1uF  [0603]
C70  1uF  [0603]
C71  1uF  [0603]
C72  1uF  [0603]
C73  1uF  [0603]
C74  1uF  [0603]
C75  1uF  [0603]
C76  1uF  [0603]
C77  1uF  [0603]
C78  1uF  [0603]
C79  1uF  [0603]
C80  1uF  [0603]
C81  1uF  [0603]
C82  1nF  [0402]
C83  1nF  [0402]
C84  1nF  [0402]
C85  1nF  [0402]
FF2  SY10EP31VKG(SINGLE DFF)  [MSOP8N]
FF3  SY89321LMG(LVPECL-LVTTL)  [DFN_8PIN]
FO5  ADP-2-9(PWR SPLITTER)  [PWR SPLITTER]
J6  SMA_R/A  [SMA_R/A]
J7  LEMO_R/A  [LEMO_R/A]
OA1  LT1395CS5(OPAMP)  [SOT23_5PIN]
POT3  3296W-1-103RLF(10 TURN 10K POT)  [10K POT]
R89  127  [0402]
R90  127  [0402]
R91  49.9  [0402]
R92  82.5  [0402]
R93  82.5  [0402]
R94  49.9  [0402]
R95  49.9  [0402]
R96  49.9  [0402]
R97  49.9  [0402]
R98  127  [0402]
R99  49.9  [0402]
R100  49.9  [0402]
R101  82.5  [0402]
R102  49.9  [0402]
R103  49.9  [0402]
R104  49.9  [0402]
R105  1K  [0402]
R106  4.02K  [0402]
TP17  10MHz  [SMD_TP]
TP30  VCO  [Test Point]
U2  CVCO55CL-0490-0540(508.9MHz VCO)  [QFN_16pin Variant]
U3  KAT1108E( 8BIT DIP SWITCH)  [8 BIT DIP SWITCH]
U4  SN74HC682DW(2X8 COM)  [SOIC_20pin]
U5  KAT1108E( 8BIT DIP SWITCH)  [8 BIT DIP SWITCH]

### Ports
TEST RF CLK (in), TEST RF CLK (out), TEST_DFF_N (in), TEST_DFF_N (out), TEST_DFF_P (in), TEST_DFF_P (out), ~{P=Q} (in), ~{P=Q} (out)

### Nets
3V3AUX: B3.8(VCC) B3.13(VCC) BC5.1(VCC) BC5.8(VCC) BC5.13(VCC) BC5.32(VCC) BC6.16(VCC) C70.2 C72.2 C73.2 C74.1 C75.2 C76.1 C77.2 C78.1 C79.2 C80.1 C81.2 C82.2 C85.2 FF2.8(VCC) FF3.8(VCC) R89.2 R90.2 R97.1 R98.2 R99.1 U3.9(+) U4.20(VCC) U5.9(+)
5VAUX: C69.1 C71.1 POT3.1(CCW) U2.14(VCC)
+5V: OA1.5(VCC)
-5V: OA1.2(VEE)
GND: B3.7(VEE) B3.14(VEE) B3.17(GND) BC5.9(VEE) BC5.28(VEE) BC6.8(GND) BC6.12(~{CE}) BC6.14(~{OE}) C69.2 C70.1 C71.2 C72.1 C73.1 C74.2 C75.1 C76.2 C77.1 C78.2 C79.1 C80.2 C81.1 C84.1 FF2.1(SET) FF2.4(R) FF2.5(VEE) FF3.5(VEE) FF3.9(GND) FO5.6(GND) J6.2 J6.3 J6.4 J6.5 J7.2 J7.3 J7.4 J7.5 OA1.3(IN+) POT3.3(CW) R91.2 R92.1 R93.1 R96.1 R100.1 R101.2 R102.2 U2.1(GND) U2.3(GND) U2.4(GND) U2.5(GND) U2.6(GND) U2.7(GND) U2.8(GND) U2.9(GND) U2.11(GND) U2.12(GND) U2.13(GND) U2.15(GND) U2.16(GND) U3.10(-) U4.10(GND) U5.10(-)
TEST RF CLK-1_N: B3.9(~{Q2}) BC5.23(CLK_N) R95.1  [also labelled TEST RF CLK_N]
TEST RF CLK-1_P: B3.10(Q2) BC5.22(CLK_P) R94.1  [also labelled TEST RF CLK_P]
TEST RF CLK-2_N: FF2.2(D) FF2.6(~{Q}) FF3.3(~{IN}) R103.1 ; port TEST_DFF_N  [also labelled TEST RF CLK-2_N2]
TEST RF CLK-2_P: FF2.7(Q) FF3.2(IN) R104.1 ; port TEST_DFF_P  [also labelled TEST RF CLK-2_P2]
NetB3_1: B3.1(D) C83.2
NetB3_2: B3.2(~{D}) B3.16(VT) C84.2
NetB3_11: B3.11(~{Q1}) R90.1 R93.2
NetB3_12: B3.12(Q1) R89.1 R92.2
NetBC5_7: BC5.7(TCLD) R97.2
NetBC5_12: BC5.12(~{TC}) FF2.3(CLK) R98.1 R101.1
NetBC5_14: BC5.14(P7) U3.8
NetBC5_15: BC5.15(P6) U3.7
NetBC5_16: BC5.16(P5) U3.6
NetBC5_17: BC5.17(P4) U3.5
NetBC5_18: BC5.18(P3) U3.4
NetBC5_19: BC5.19(P2) U3.3
NetBC5_20: BC5.20(P1) U3.2
NetBC5_21: BC5.21(P0) U3.1
NetBC5_25: BC5.25(~{PE}) R99.2
NetBC5_26: BC5.26(~{CE}) R100.2
NetBC5_27: BC5.27(MR) R96.2
NetBC6_1: BC6.1(Q1) U4.4(P1)
NetBC6_2: BC6.2(Q2) U4.6(P2)
NetBC6_3: BC6.3(Q3) U4.8(P3)
NetBC6_4: BC6.4(Q4) U4.11(P4)
NetBC6_5: BC6.5(Q5) U4.13(P5)
NetBC6_6: BC6.6(Q6) U4.15(P6)
NetBC6_7: BC6.7(Q7) U4.17(P7)
NetBC6_10: BC6.10(~{MRC}) R106.1 U4.19(~{P=Q}) ; port ~{P=Q}
NetBC6_11: BC6.11(CCLK) BC6.13(RCLK) FF3.7(Q) TP17.1(TP)
NetBC6_15: BC6.15(Q0) U4.2(P0)
NetC68_1: C68.1 U2.10(RF_OUT)
NetC68_2: C68.2 FO5.1(INPUT_S)
NetC82_1: C82.1 R91.1 R94.2 R95.2
NetC83_1: C83.1 FO5.3(OUTPUT_1) ; port TEST RF CLK
NetC85_1: C85.1 R102.1 R103.2 R104.2
NetFO5_2: FO5.2(OUTPUT_4) FO5.5(OUTPUT_3)
NetFO5_4: FO5.4(OUTPUT_2) J6.1
NetJ7_1: J7.1 OA1.1(OUT) R105.2
NetOA1_4: OA1.4(IN-) R105.1 R106.2
NetPOT3_2: POT3.2(Wiper) TP30.1(TP) U2.2(VT)
NetU4_3: U4.3(Q0) U5.1
NetU4_5: U4.5(Q1) U5.2
NetU4_7: U4.7(Q2) U5.3
NetU4_9: U4.9(Q3) U5.4
NetU4_12: U4.12(Q4) U5.5
NetU4_14: U4.14(Q5) U5.6
NetU4_16: U4.16(Q6) U5.7
NetU4_18: U4.18(Q7) U5.8

Not connected (* = marked no-connect by the designer): B3 3(NC) 4(NC) 5(NC) 6(NC) 15(VREF); BC5 2(Q3) 3(Q4) 4(Q5) 5(Q6) 6(Q7) 10(COUT_P) 11(COUT_N) 24(VBB) 29(Q0) 30(Q1) 31(Q2); BC6 9(~{RCO}); FF3 1(NC) 4(VBB) 6(NC); U4 1(~{P<Q})

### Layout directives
differential pair: TEST RF CLK-1_N, TEST RF CLK-1_P, TEST RF CLK-2_N, TEST RF CLK-2_P
net class RF: (no net found under the mark)

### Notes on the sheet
- 508.9MHz sine wave generator
- Bypass caps for power pins.
- (near U2) 3dBm
- 100KHz NIM generator
- (near B3) 508.9MHZ LVPECL
- (near FF2) 20MHZ LVPECL
- LSB
- 1
- (near R100) 1
- (near U3) SET TO 231
- (near U3) MSB
- 0
- 10MHZ LVTTL
- Notes:
- -Low output: 0A
- -High output: -20mA
- -Pluse width 100ns(50 RF CLK CYCLES)
- --Outputs 1% dutycycle squarewave at 100KHz
- --pluse width can be adjusted from counter and opamp
- --Divider set to divide by 206 (508.9MHz in, 20MHz out)
- --D flip flop takes in 20MHz clock and give 50% duty cycle 10MHz clock
- (near U5) LSB
- (near U5) 0
- (near U5) 1
- (near U5) SET TO 99
- (near U5) MSB
- Labels drawn without touching a wire or pin: CH3_N

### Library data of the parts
B3 = ADCLK925BCPZ-R7(Sine-LVPECL): as B1 on sheet IDL_17_004_A2
BC5 = MC100EP016A(8_bit_counter): as BC1 on sheet IDL_17_004_A4
BC6 = 74HC590PW(8_bit_counter): IC BINARY COUNTER 8BIT 16-TSSOP; Manufacturer: NXP Semiconductors; Manufacturer part #: 74HC590PW,118
C68 C82-C85 = 1nF: as C7 on sheet IDL_17_004_A2
C69-C81 = 1uF: as C1 on sheet IDL_17_004_A2
FF2 = SY10EP31VKG(SINGLE DFF): IC D-TYPE POS TRG SNGL 8MSOP; Manufacturer: Micrel Inc.
FF3 = SY89321LMG(LVPECL-LVTTL): IC TRANSLATOR LVPECL-LVTTL 8-MLF; Manufacturer: Micrel Inc.; Manufacturer part #: SY89321LMG TR
FO5 = ADP-2-9(PWR DIV): PWR SPL CMB / SM / RoHS5; Manufacturer: MINI_CIRCUITS
J6 = SMA_R/A: as J1 on sheet IDL_17_004_A2
J7 = LEMO_R/A: as J5 on sheet IDL_17_004_A3
OA1 = LT1395CS5(OPAMP): IC OPAMP CFA 400MHZ TSOT23-5; Manufacturer: Linear Technology; Manufacturer part #: LT1395CS5#TRMPBF
POT3 = 3296W-1-103RLF(10 TURN 10K POT): TRIMMER 10K OHM 0.5W PC PIN; Manufacturer: Bourns Inc.
R89 R90 R98 = 127: as R9 on sheet IDL_17_004_A2
R91 R94-R97 R99 R100 R102-R104 = 49.9: as R3 on sheet IDL_17_004_A2
R92 R93 R101 = 82.5: as R11 on sheet IDL_17_004_A2
R105 = 1K: as R32 on sheet IDL_17_004_A3
R106 = 4.02K: as R33 on sheet IDL_17_004_A3
TP17 = SMD_TP: SURFACE MOUNT TEST POINT
TP30 = TP: TEST POINT PC MINI .040"D BLACK; Manufacturer: Keystone Electronics; Manufacturer part #: 5001
U2 = CVCO55CL-0490-0540(508.9MHz VCO): OSC VCO 490-540MHZ SMD .5X.5"; Manufacturer: ON Semiconductor
U3 U5 = KAT1108E( 8BIT DIP SWITCH): DIP SW 8POS EXTEND ACTUATOR 24V; Manufacturer: Samsung Electro-Mechanics America, Inc.; Manufacturer part #: CL10B103KB8NCNC
U4 = SN74HC682DW(2X8 COM): IC COMPARATOR MAGNITUDE 20SOIC; Manufacturer: Texas Instruments

## Sheet IDL_17_004_A6.SchDoc: XTD Module Controller
size 401 x 291 mm
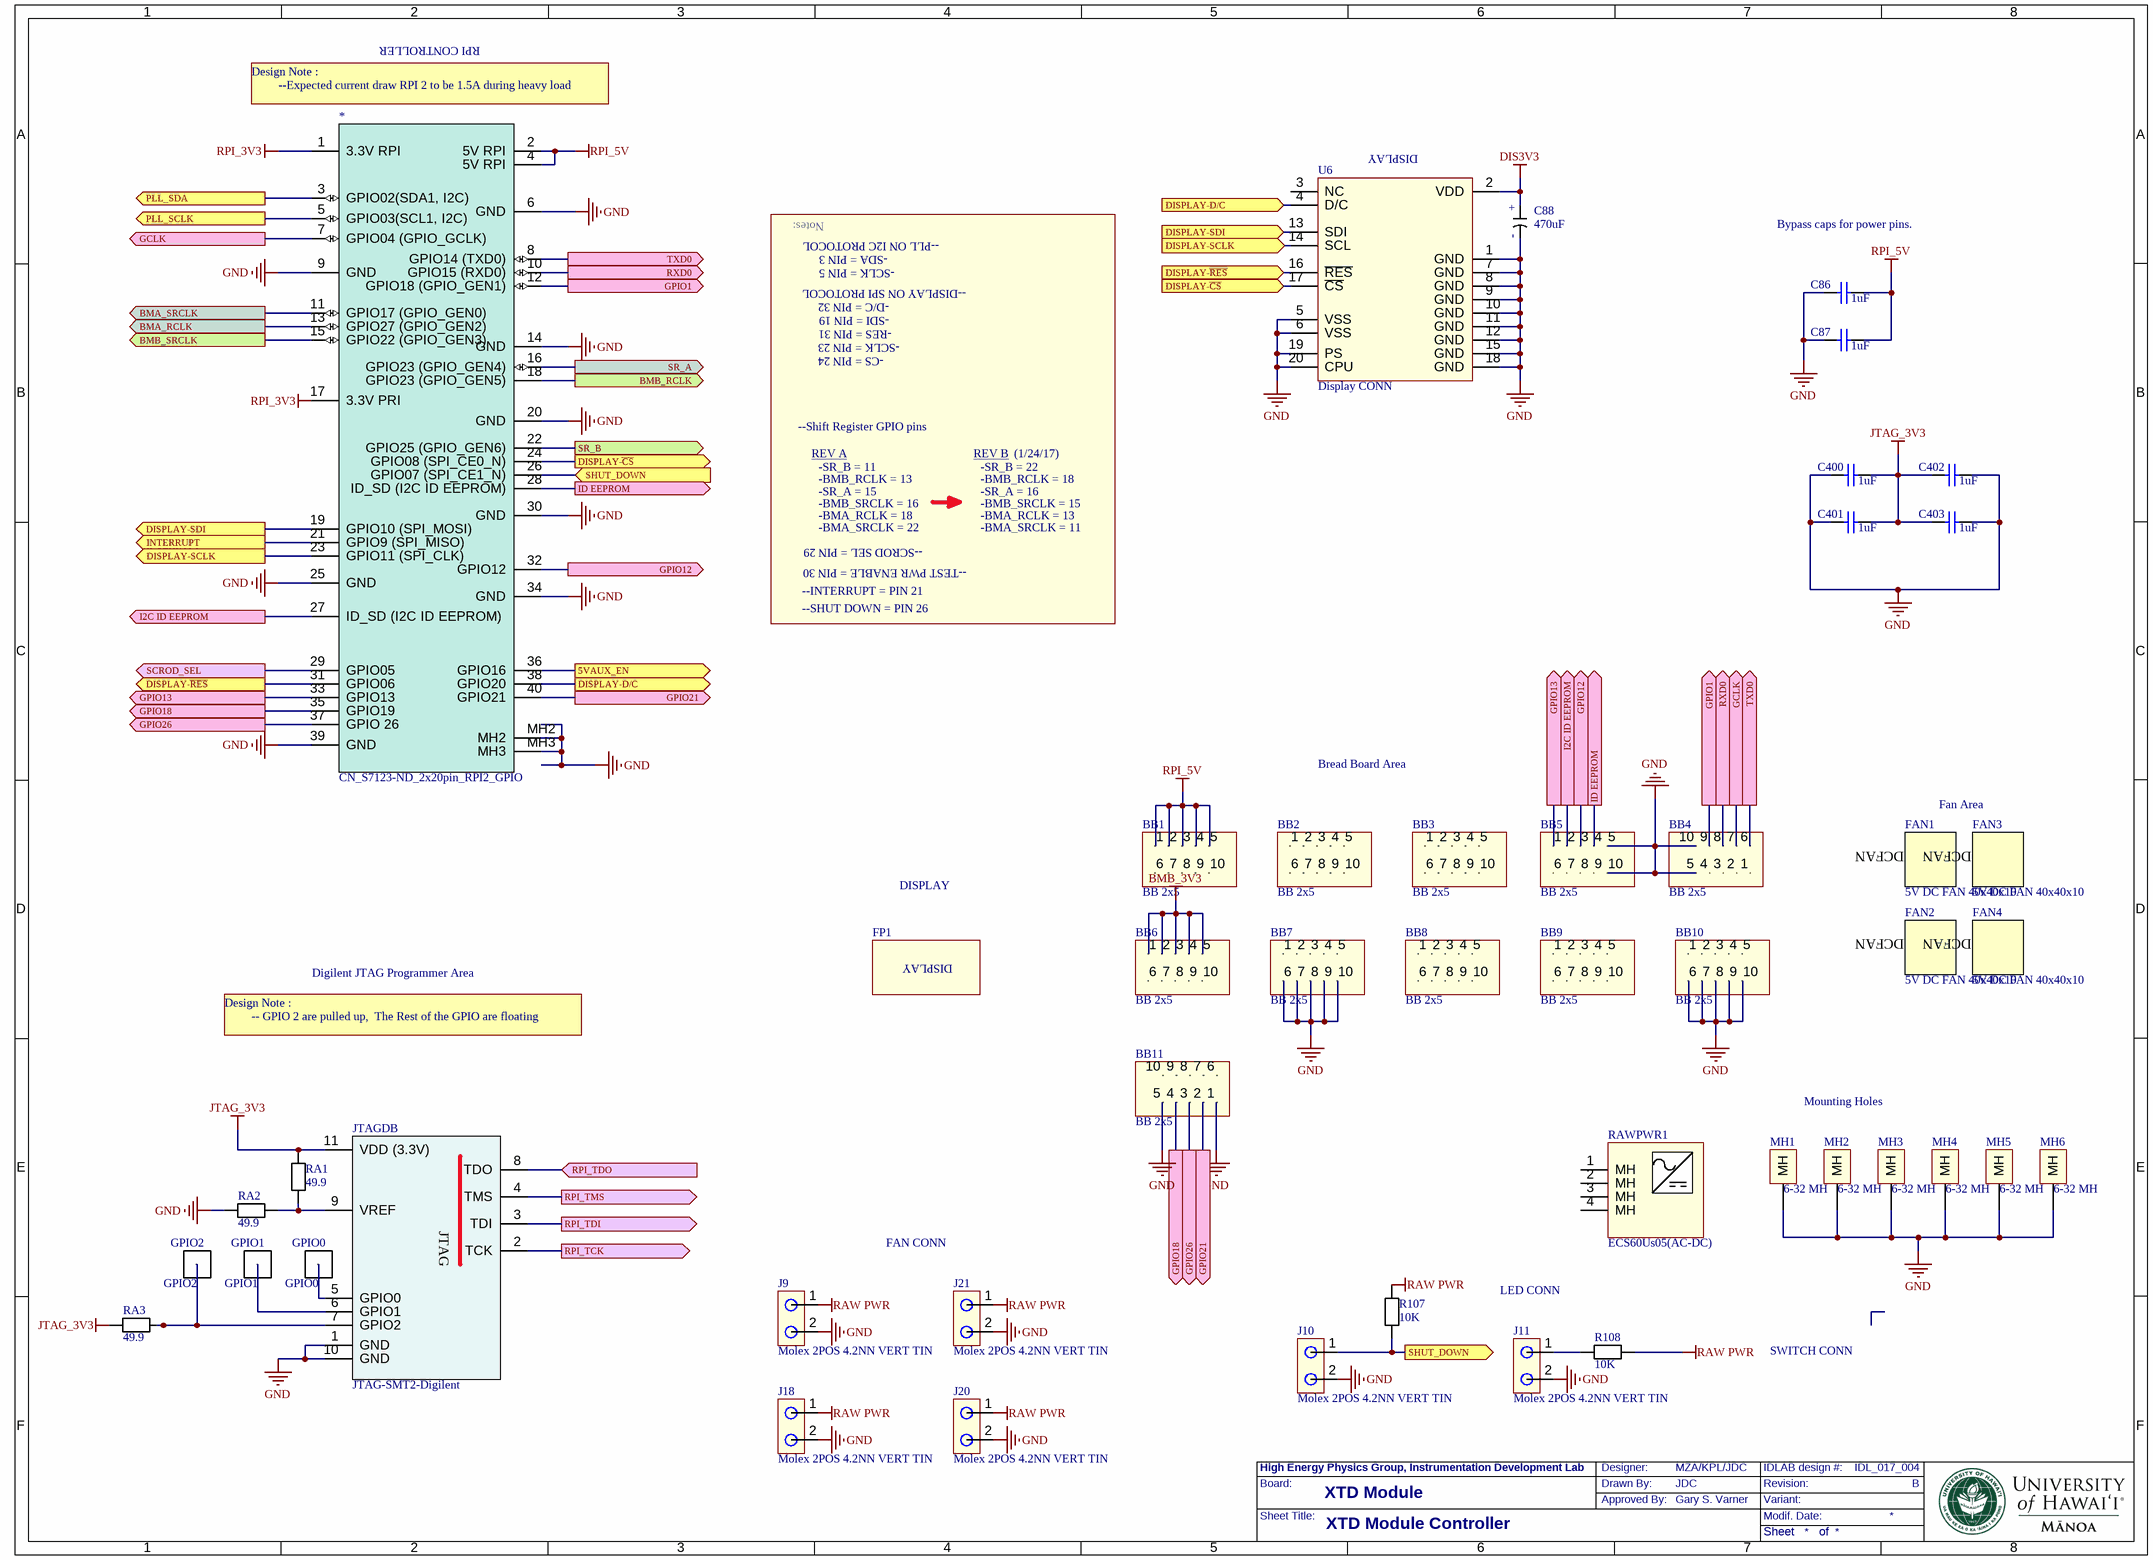
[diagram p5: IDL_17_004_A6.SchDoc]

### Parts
*  CN_S7123-ND_2x20pin_RPI2_GPIO  [RPI_2/RPI_3]
BB1  BB 2x5  [BREAD BOARD]
BB2  BB 2x5  [BREAD BOARD]
BB3  BB 2x5  [BREAD BOARD]
BB4  BB 2x5  [BREAD BOARD]
BB5  BB 2x5  [BREAD BOARD]
BB6  BB 2x5  [BREAD BOARD]
BB7  BB 2x5  [BREAD BOARD]
BB8  BB 2x5  [BREAD BOARD]
BB9  BB 2x5  [BREAD BOARD]
BB10  BB 2x5  [BREAD BOARD]
BB11  BB 2x5  [BREAD BOARD]
C86  1uF  [0603]
C87  1uF  [0603]
C88  470uF  [CAP_TH]
C400  1uF  [0603]
C401  1uF  [0603]
C402  1uF  [0603]
C403  1uF  [0603]
FAN1  5V DC FAN 40x40x10  [603-2014-ND]
FAN2  5V DC FAN 40x40x10  [603-2014-ND]
FAN3  5V DC FAN 40x40x10  [603-2014-ND]
FAN4  5V DC FAN 40x40x10  [603-2014-ND]
FP1  DISPLAY  [DISPLAY]
GPIO0  GPIO0  [SMD_TP]
GPIO1  GPIO1  [SMD_TP]
GPIO2  GPIO2  [SMD_TP]
J9  Molex 2POS 4.2NN VERT TIN  [Molex 2POS]
J10  Molex 2POS 4.2NN VERT TIN  [Molex 2POS]
J11  Molex 2POS 4.2NN VERT TIN  [Molex 2POS]
J18  Molex 2POS 4.2NN VERT TIN  [Molex 2POS]
J20  Molex 2POS 4.2NN VERT TIN  [Molex 2POS]
J21  Molex 2POS 4.2NN VERT TIN  [Molex 2POS]
JTAGDB  JTAG-SMT2-Digilent  [Digilent JTAG Programmer SMD]
MH1  6-32 MH  [6-32 MH]
MH2  6-32 MH  [6-32 MH]
MH3  6-32 MH  [6-32 MH]
MH4  6-32 MH  [6-32 MH]
MH5  6-32 MH  [6-32 MH]
MH6  6-32 MH  [6-32 MH]
R107  10K  [0402]
R108  10K  [0402]
RA1  49.9  [0402]
RA2  49.9  [0402]
RA3  49.9  [0402]
RAWPWR1  ECS60Us05(AC-DC)  [ECS60US05]
U6  Display CONN  [DISPLAY CONN]

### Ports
5VAUX_EN (out), BMA_RCLK (out), BMA_SRCLK (out), BMB_RCLK (out), BMB_SRCLK (out), DISPLAY-D/C (in), DISPLAY-D/C (out), DISPLAY-SCLK (in), DISPLAY-SCLK (out), DISPLAY-SDI (in), DISPLAY-SDI (out), DISPLAY-~{CS} (in), DISPLAY-~{CS} (out), DISPLAY-~{RES} (in), DISPLAY-~{RES} (out), GCLK (out), GPIO1 (out), GPIO12 (out), GPIO13 (out), GPIO18 (out), GPIO21 (out), GPIO26 (out), I2C ID EEPROM (out), ID EEPROM (out), INTERRUPT (out), PLL_SCLK (out), PLL_SDA (out), RPI_TCK (out), RPI_TDI (out), RPI_TDO (in), RPI_TMS (out), RXD0 (out), SCROD_SEL (out), SHUT_DOWN (in), SHUT_DOWN (out), SR_A (out), SR_B (out), TXD0 (out)

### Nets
BMB_3V3: BB6.1 BB6.2 BB6.3 BB6.4 BB6.5
DIS3V3: C88.1 U6.2(VDD)
GND: *.6(GND) *.9(GND) *.14(GND) *.20(GND) *.25(GND) *.30(GND) *.34(GND) *.39(GND) *.MH2 *.MH3 BB4.5 BB4.10 BB5.5 BB5.10 BB7.6 BB7.7 BB7.8 BB7.9 BB7.10 BB10.6 BB10.7 BB10.8 BB10.9 BB10.10 BB11.1 BB11.5 C86.2 C87.2 C88.2 C400.2 C401.2 C402.1 C403.1 J9.2 J10.2 J11.2 J18.2 J20.2 J21.2 JTAGDB.1(GND) JTAGDB.10(GND) MH1.1(MH) MH2.1(MH) MH3.1(MH) MH4.1(MH) MH5.1(MH) MH6.1(MH) RA2.2 U6.1(GND) U6.5(VSS) U6.6(VSS) U6.7(GND) U6.8(GND) U6.9(GND) U6.10(GND) U6.11(GND) U6.12(GND) U6.15(GND) U6.18(GND) U6.19(PS) U6.20(CPU)
JTAG_3V3: C400.1 C401.1 C402.2 C403.2 JTAGDB.11(VDD_(3.3V)) RA1.2 RA3.2
RAW PWR: J9.1 J18.1 J20.1 J21.1 R107.2 R108.1
RPI_3V3: *.1(3.3V_RPI) *.17(3.3V_PRI)
RPI_5V: *.2(5V_RPI) *.4(5V_RPI) BB1.1 BB1.2 BB1.3 BB1.4 BB1.5 C86.1 C87.1
BMA_RCLK: *.13(GPIO27_(GPIO_GEN2)) ; port BMA_RCLK
BMA_SRCLK: *.11(GPIO17_(GPIO_GEN0)) ; port BMA_SRCLK
BMB_RCLK: *.18(GPIO23_(GPIO_GEN5)) ; port BMB_RCLK
BMB_SRCLK: *.15(GPIO22_(GPIO_GEN3)) ; port BMB_SRCLK
SR_A: *.16(GPIO23_(GPIO_GEN4)) ; port SR_A
SR_B: *.22(GPIO25_(GPIO_GEN6)) ; port SR_B
TCK: JTAGDB.2(TCK) ; port RPI_TCK
TDI: JTAGDB.3(TDI) ; port RPI_TDI
TDO: JTAGDB.8(TDO) ; port RPI_TDO
TMS: JTAGDB.4(TMS) ; port RPI_TMS
Net*_3: *.3(GPIO02(SDA1,_I2C)) ; port PLL_SDA
Net*_5: *.5(GPIO03(SCL1,_I2C)) ; port PLL_SCLK
Net*_7: *.7(GPIO04_(GPIO_GCLK)) BB4.7 ; port GCLK
Net*_8: *.8(GPIO14_(TXD0)) BB4.6 ; port TXD0
Net*_10: *.10(GPIO15_(RXD0)) BB4.8 ; port RXD0
Net*_12: *.12(GPIO18_(GPIO_GEN1)) BB4.9 ; port GPIO1
Net*_19: *.19(GPIO10_(SPI_MOSI)) U6.13(SDI) ; port DISPLAY-SDI
Net*_21: *.21(GPIO9_(SPI_MISO)) ; port INTERRUPT
Net*_23: *.23(GPIO11_(SPI_CLK)) U6.14(SCL) ; port DISPLAY-SCLK
Net*_24: *.24(GPIO08_(SPI_CE0_N)) U6.17(~{CS}) ; port DISPLAY-~{CS}
Net*_26: *.26(GPIO07_(SPI_CE1_N)) J10.1 R107.1 ; port SHUT_DOWN
Net*_27: *.27(ID_SD_(I2C_ID_EEPROM)) BB5.2 ; port I2C ID EEPROM
Net*_28: *.28(ID_SD_(I2C_ID_EEPROM)) BB5.4 ; port ID EEPROM
Net*_29: *.29(GPIO05) ; port SCROD_SEL
Net*_31: *.31(GPIO06) U6.16(~{RES}) ; port DISPLAY-~{RES}
Net*_32: *.32(GPIO12) BB5.3 ; port GPIO12
Net*_33: *.33(GPIO13) BB5.1 ; port GPIO13
Net*_35: *.35(GPIO19) BB11.4 ; port GPIO18
Net*_36: *.36(GPIO16) ; port 5VAUX_EN
Net*_37: *.37(GPIO_26) BB11.3 ; port GPIO26
Net*_38: *.38(GPIO20) U6.4(D/C) ; port DISPLAY-D/C
Net*_40: *.40(GPIO21) BB11.2 ; port GPIO21
NetGPIO0_1: GPIO0.1(TP) JTAGDB.5(GPIO0)
NetGPIO1_1: GPIO1.1(TP) JTAGDB.6(GPIO1)
NetGPIO2_1: GPIO2.1(TP) JTAGDB.7(GPIO2) RA3.1
NetJ11_1: J11.1 R108.2
NetJTAGDB_9: JTAGDB.9(VREF) RA1.1 RA2.1

Not connected (* = marked no-connect by the designer): BB1 6 7 8 9 10; BB2 1 2 3 4 5 6 7 8 9 10; BB3 1 2 3 4 5 6 7 8 9 10; BB4 1 2 3 4; BB5 6 7 8 9; BB6 6 7 8 9 10; BB7 1 2 3 4 5; BB8 1 2 3 4 5 6 7 8 9 10; BB9 1 2 3 4 5 6 7 8 9 10; BB10 1 2 3 4 5; BB11 6 7 8 9 10; RAWPWR1 1(MH) 2(MH) 3(MH) 4(MH); U6 3(NC)

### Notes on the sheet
- (near *) Design Note :
  --Expected current draw RPI 2 to be 1.5A during heavy load
- RPI CONTROLLER
- (near U6) DISPLAY
- Notes:
- --PLL ON I2C PROTOCOL
- Bypass caps for power pins.
- -SDA = PIN 3
- -D/C = PIN 32
- -SCLK = PIN 5
- --DISPLAY ON SPI PROTOCOL
- -CS = PIN 24
- -SDI = PIN 19
- -RES = PIN 31
- -SCLK = PIN 23
- --Shift Register GPIO pins
- REV A
- -BMB_RCLK = 13
- -SR_A = 15
- -SR_B = 11
- REV B
- -BMB_RCLK = 18
- -SR_A = 16
- -SR_B = 22
- (1/24/17)
- --TEST PWR ENABLE = PIN 30
- -BMA_SRCLK = 22
- -BMB_SRCLK = 16
- -BMA_RCLK = 18
- --SCROD SEL = PIN 29
- -BMA_SRCLK = 11
- -BMB_SRCLK = 15
- -BMA_RCLK = 13
- --INTERRUPT = PIN 21
- --SHUT DOWN = PIN 26
- Bread Board Area
- (near FAN3) Fan Area
- Design Note :
  -- GPIO 2 are pulled up,  The Rest of the GPIO are floating
- Digilent JTAG Programmer Area
- Mounting Holes
- FAN CONN
- LED CONN
- SWITCH CONN

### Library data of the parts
* = CN_S7123-ND_2x20pin_RPI2_GPIO: CONN HEADER FMAL 40PS.1" DL GOLD; Manufacturer: Sullins Connector Solutions; Manufacturer No: PPPC202LFBN-RC; Tech: THDW
C86 C87 C400-C403 = 1uF: as C1 on sheet IDL_17_004_A2
C88 = 470uF: CAP ALUM 470UF 20% 50V RADIAL; Manufacturer: Nichicon; Manufacturer part #: UPW1H471MHD
FP1 = DISPLAY: DOUBLE NIM FRONT PANEL
GPIO0-GPIO2 = SMD_TP: SURFACE MOUNT TEST POINT
J9-J11 J18 J20 J21 = Molex 2POS 4.2NN VERT TIN: CONN HEADER 2POS 4.2MM VERT TIN; Manufacturer: Molex Inc.; Manufacturer part #: 0009652048
MH1-MH6 = 6-32 MH: 6-32 MOUNTING HOLE
R107 R108 = 10K: as R1 on sheet IDL_17_004_A2
RA1-RA3 = 49.9: as R3 on sheet IDL_17_004_A2
RAWPWR1 = ECS60Us05(AC-DC): AC-DC convertor; Manufacturer: XP Power
U6 = Display CONN: DISPLAY FULL COLOR OLED 1.69"; Manufacturer: Newhaven Display Intl; Manufacturer part #: NHD-1.69-160128UGC3

## Sheet IDL_17_004_A7.SchDoc: JTAG
size 401 x 291 mm; DocumentNumber: 3; SheetNumber: 3; SheetTotal: 3
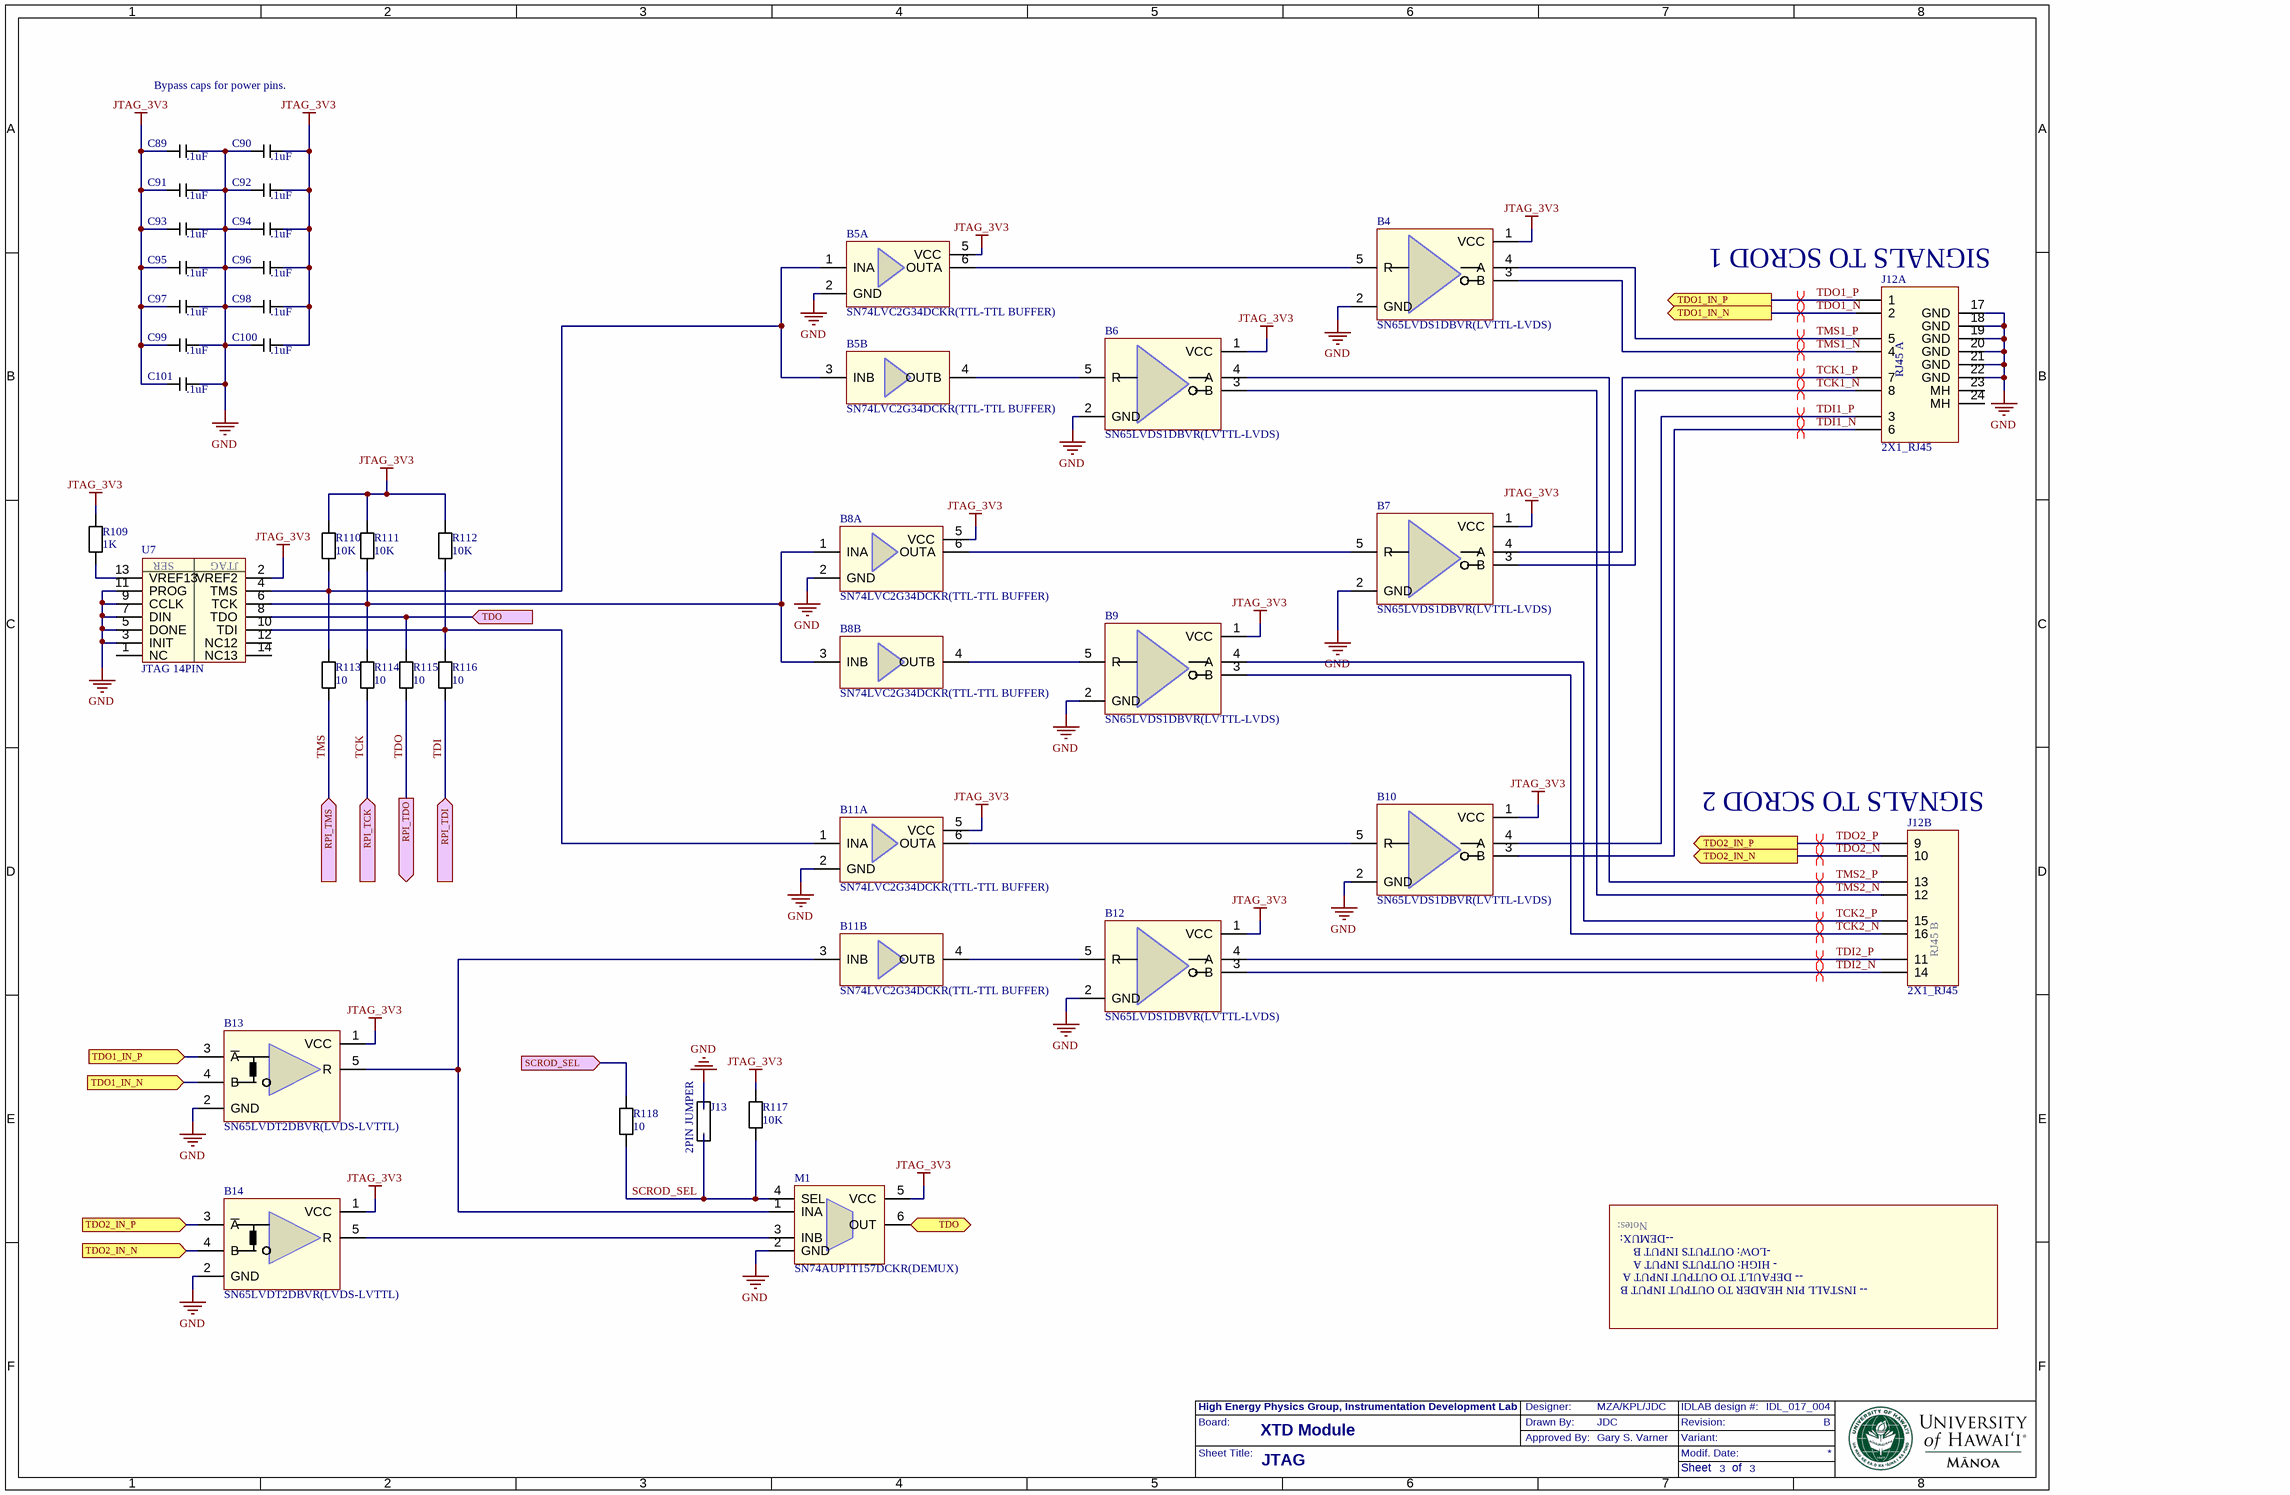
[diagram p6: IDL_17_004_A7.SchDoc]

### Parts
B4  SN65LVDS1DBVR(LVTTL-LVDS)  [SOT23_5PIN]
B5  SN74LVC2G34DCKR(TTL-TTL BUFFER)  [TSSOP_6PIN]  (parts A,B of 2)
B6  SN65LVDS1DBVR(LVTTL-LVDS)  [SOT23_5PIN]
B7  SN65LVDS1DBVR(LVTTL-LVDS)  [SOT23_5PIN]
B8  SN74LVC2G34DCKR(TTL-TTL BUFFER)  [TSSOP_6PIN]  (parts A,B of 2)
B9  SN65LVDS1DBVR(LVTTL-LVDS)  [SOT23_5PIN]
B10  SN65LVDS1DBVR(LVTTL-LVDS)  [SOT23_5PIN]
B11  SN74LVC2G34DCKR(TTL-TTL BUFFER)  [TSSOP_6PIN]  (parts A,B of 2)
B12  SN65LVDS1DBVR(LVTTL-LVDS)  [SOT23_5PIN]
B13  SN65LVDT2DBVR(LVDS-LVTTL)  [SOT23_5PIN]
B14  SN65LVDT2DBVR(LVDS-LVTTL)  [SOT23_5PIN]
C89  .1uF  [0603]
C90  .1uF  [0603]
C91  .1uF  [0603]
C92  .1uF  [0603]
C93  .1uF  [0603]
C94  .1uF  [0603]
C95  .1uF  [0603]
C96  .1uF  [0603]
C97  .1uF  [0603]
C98  .1uF  [0603]
C99  .1uF  [0603]
C100  .1uF  [0603]
C101  .1uF  [0603]
J12  2X1_RJ45  [2X1 RJ45]  (parts A,B of 2)
J13  2PIN JUMPER  [2 PIN HEADER]
M1  SN74AUP1T157DCKR(DEMUX)  [TSSOP_6PIN]
R109  1K  [0402]
R110  10K  [0402]
R111  10K  [0402]
R112  10K  [0402]
R113  10  [0402]
R114  10  [0402]
R115  10  [0402]
R116  10  [0402]
R117  10K  [0402]
R118  10  [0402]
U7  JTAG 14PIN  [JTAG_14PIN_2MM_VERT]

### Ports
RPI_TCK (in), RPI_TDI (in), RPI_TDO (out), RPI_TMS (in), SCROD_SEL (in), TDO1_IN_N (in), TDO1_IN_N (out), TDO1_IN_P (in), TDO1_IN_P (out), TDO2_IN_N (in), TDO2_IN_N (out), TDO2_IN_P (in), TDO2_IN_P (out), TDO (in), TDO (out)

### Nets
GND: B4.2(GND) B5.2(GND) B6.2(GND) B7.2(GND) B8.2(GND) B9.2(GND) B10.2(GND) B11.2(GND) B12.2(GND) B13.2(GND) B14.2(GND) C89.2 C90.1 C91.2 C92.1 C93.2 C94.1 C95.2 C96.1 C97.2 C98.1 C99.2 C100.1 C101.2 J12.17(GND) J12.18(GND) J12.19(GND) J12.20(GND) J12.21(GND) J12.22(GND) J13.2 M1.2(GND) U7.3(INIT) U7.5(DONE) U7.7(DIN) U7.9(CCLK) U7.11(PROG)
JTAG_3V3: B4.1(VCC) B5.5(VCC) B6.1(VCC) B7.1(VCC) B8.5(VCC) B9.1(VCC) B10.1(VCC) B11.5(VCC) B12.1(VCC) B13.1(VCC) B14.1(VCC) C89.1 C90.2 C91.1 C92.2 C93.1 C94.2 C95.1 C96.2 C97.1 C98.2 C99.1 C100.2 C101.1 M1.5(VCC) R109.2 R110.2 R111.2 R112.2 R117.2 U7.2(VREF2)
SCROD_SEL: J13.1 M1.4(SEL) R117.1 R118.1
TCK: R114.2 ; port RPI_TCK
TCK1_N: B7.3(B) J12.8
TCK1_P: B7.4(A) J12.7
TCK2_N: B9.3(B) J12.16
TCK2_P: B9.4(A) J12.15
TDI: R116.2 ; port RPI_TDI
TDI1_N: B10.3(B) J12.6
TDI1_P: B10.4(A) J12.3
TDI2_N: B12.3(B) J12.14
TDI2_P: B12.4(A) J12.11
TDO: R115.2 ; port RPI_TDO
TDO1_N: B13.4(B) J12.2 ; port TDO1_IN_N
TDO1_P: B13.3(~{A}) J12.1 ; port TDO1_IN_P
TDO2_N: B14.4(B) J12.10 ; port TDO2_IN_N
TDO2_P: B14.3(~{A}) J12.9 ; port TDO2_IN_P
TMS: R113.2 ; port RPI_TMS
TMS1_N: B4.3(B) J12.4
TMS1_P: B4.4(A) J12.5
TMS2_N: B6.3(B) J12.12
TMS2_P: B6.4(A) J12.13
Net*_29: R118.2 ; port SCROD_SEL
NetB4_5: B4.5(R) B5.6(OUTA)
NetB5_1: B5.1(INA) B5.3(INB) R110.1 R113.1 U7.4(TMS)
NetB5_4: B5.4(OUTB) B6.5(R)
NetB7_5: B7.5(R) B8.6(OUTA)
NetB8_1: B8.1(INA) B8.3(INB) R111.1 R114.1 U7.6(TCK)
NetB8_4: B8.4(OUTB) B9.5(R)
NetB10_5: B10.5(R) B11.6(OUTA)
NetB11_1: B11.1(INA) R112.1 R116.1 U7.10(TDI)
NetB11_3: B11.3(INB) B13.5(R) M1.1(INA)
NetB11_4: B11.4(OUTB) B12.5(R)
NetB14_5: B14.5(R) M1.3(INB)
NetM1_6: M1.6(OUT) R115.1 U7.8(TDO) ; port TDO
NetR109_1: R109.1 U7.13(VREF13)

Not connected (* = marked no-connect by the designer): J12 23(MH) 24(MH); U7 1(NC) 12(NC12) 14(NC13)

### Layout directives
differential pair: TCK1_N, TCK1_P, TCK2_N, TCK2_P, TDI1_N, TDI1_P, TDI2_N, TDI2_P, TDO1_N, TDO1_P, TDO2_N, TDO2_P, TMS1_N, TMS1_P, TMS2_N, TMS2_P

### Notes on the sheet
- Bypass caps for power pins.
- (near J12) SIGNALS TO SCROD 1
- (near J12) SIGNALS TO SCROD 2
- Notes:
- --DEMUX:
- -LOW: OUTPUTS INPUT B
- - HIGH: OUTPUTS INPUT A
- -- DEFAULT TO OUTPUT INPUT A
- -- INSTALL PIN HEADER TO OUTPUT INPUT B

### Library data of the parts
B4 B6 B7 B9 B10 B12 = SN65LVDS1DBVR(LVTTL-LVDS): IC HIGH DIFF LINE DRIVER SOT23-5; Manufacturer: Texas Instruments
B5 B8 B11 = SN74LVC2G34DCKR(TTL-TTL BUFFER): IC BUFFER DUAL NON-INV SC706; Manufacturer: Texas Instruments
B13 B14 = SN65LVDT2DBVR(LVDS-LVTTL): IC DIFF LINE RECEIVER SOT-23-5; Manufacturer: Texas Instruments
C89-C101 = .1uF: as C29 on sheet IDL_17_004_A3
J12 = 2X1_RJ45: as J2 on sheet IDL_17_004_A2
J13 = 2PIN JUMPER: TWO PIN JUMPER
M1 = SN74AUP1T157DCKR(DEMUX): IC BUFF/MUX SCHMITT-TRIG SC70-6; Manufacturer: Texas Instruments
R109 = 1K: as R32 on sheet IDL_17_004_A3
R110-R112 R117 = 10K: as R1 on sheet IDL_17_004_A2
R113-R116 R118 = 10: RES SMD 10 OHM 5% 1/16W 0402; Manufacturer: Samsung Electro-Mechanics America, Inc.; Manufacturer part #: RC1005J100CS
U7 = JTAG 14PIN: CONN HEADER 14POS 2MM GOLD DIP; Manufacturer: Hirose Electric Co Ltd; Manufacturer part #: A3C-14P-2DSA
